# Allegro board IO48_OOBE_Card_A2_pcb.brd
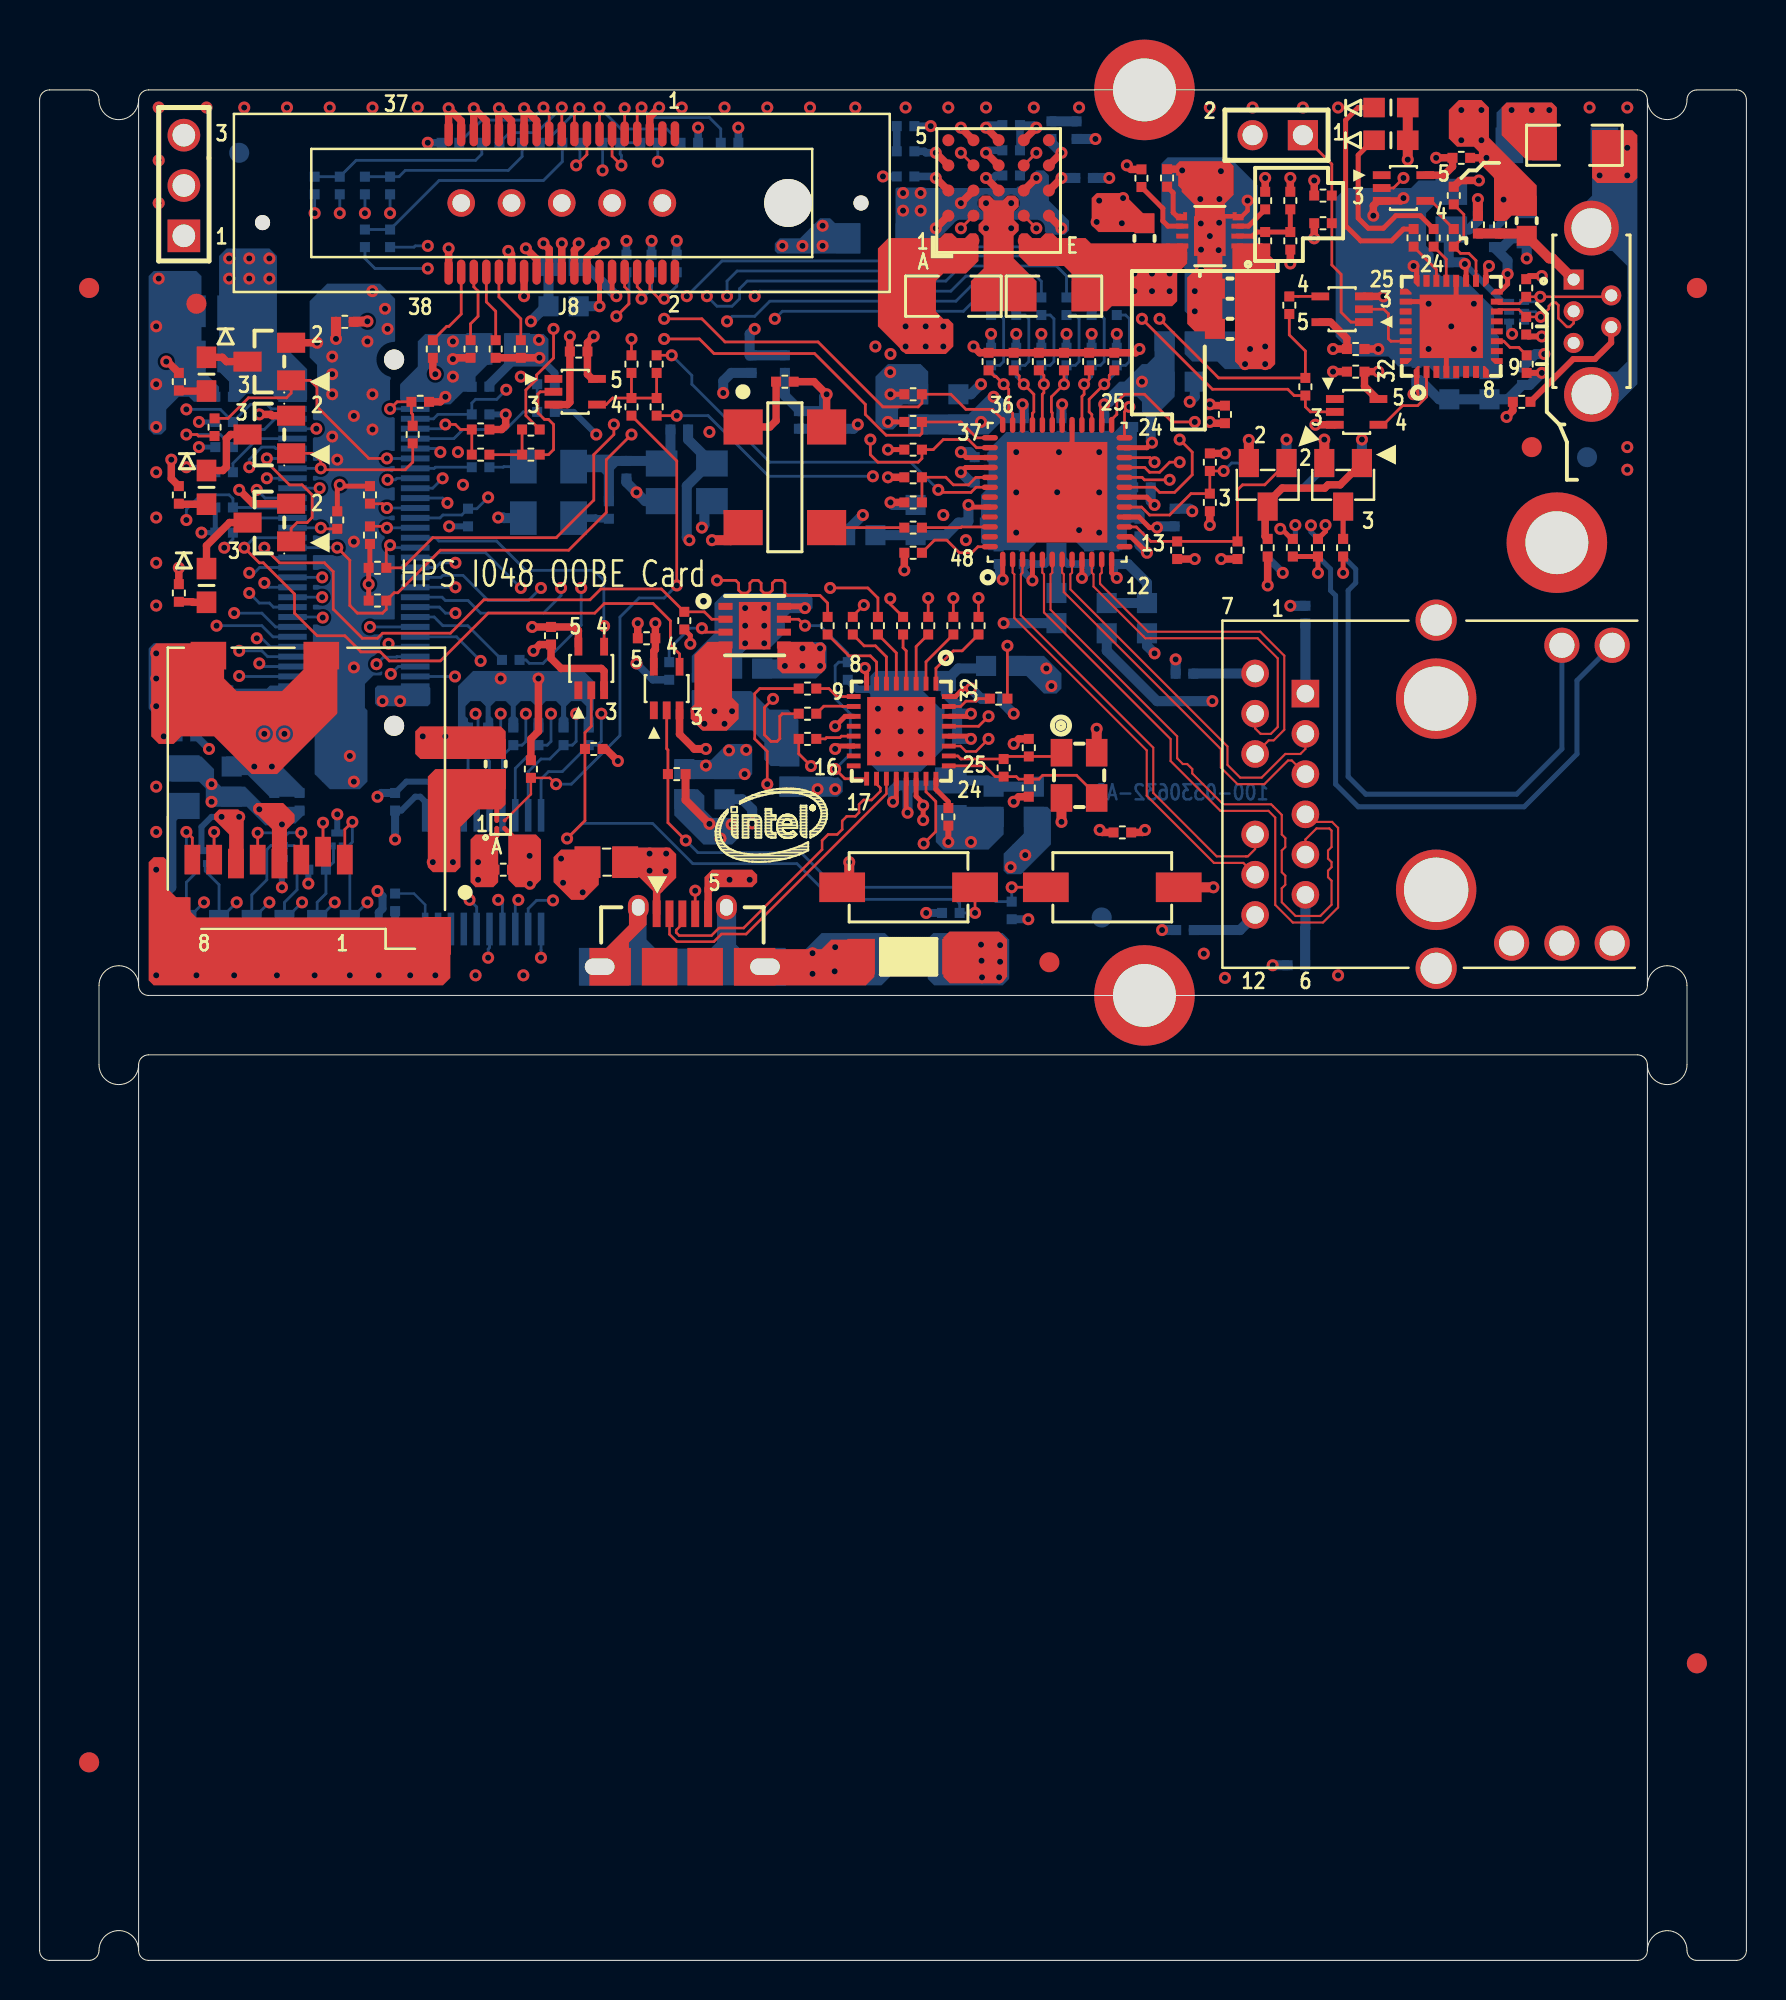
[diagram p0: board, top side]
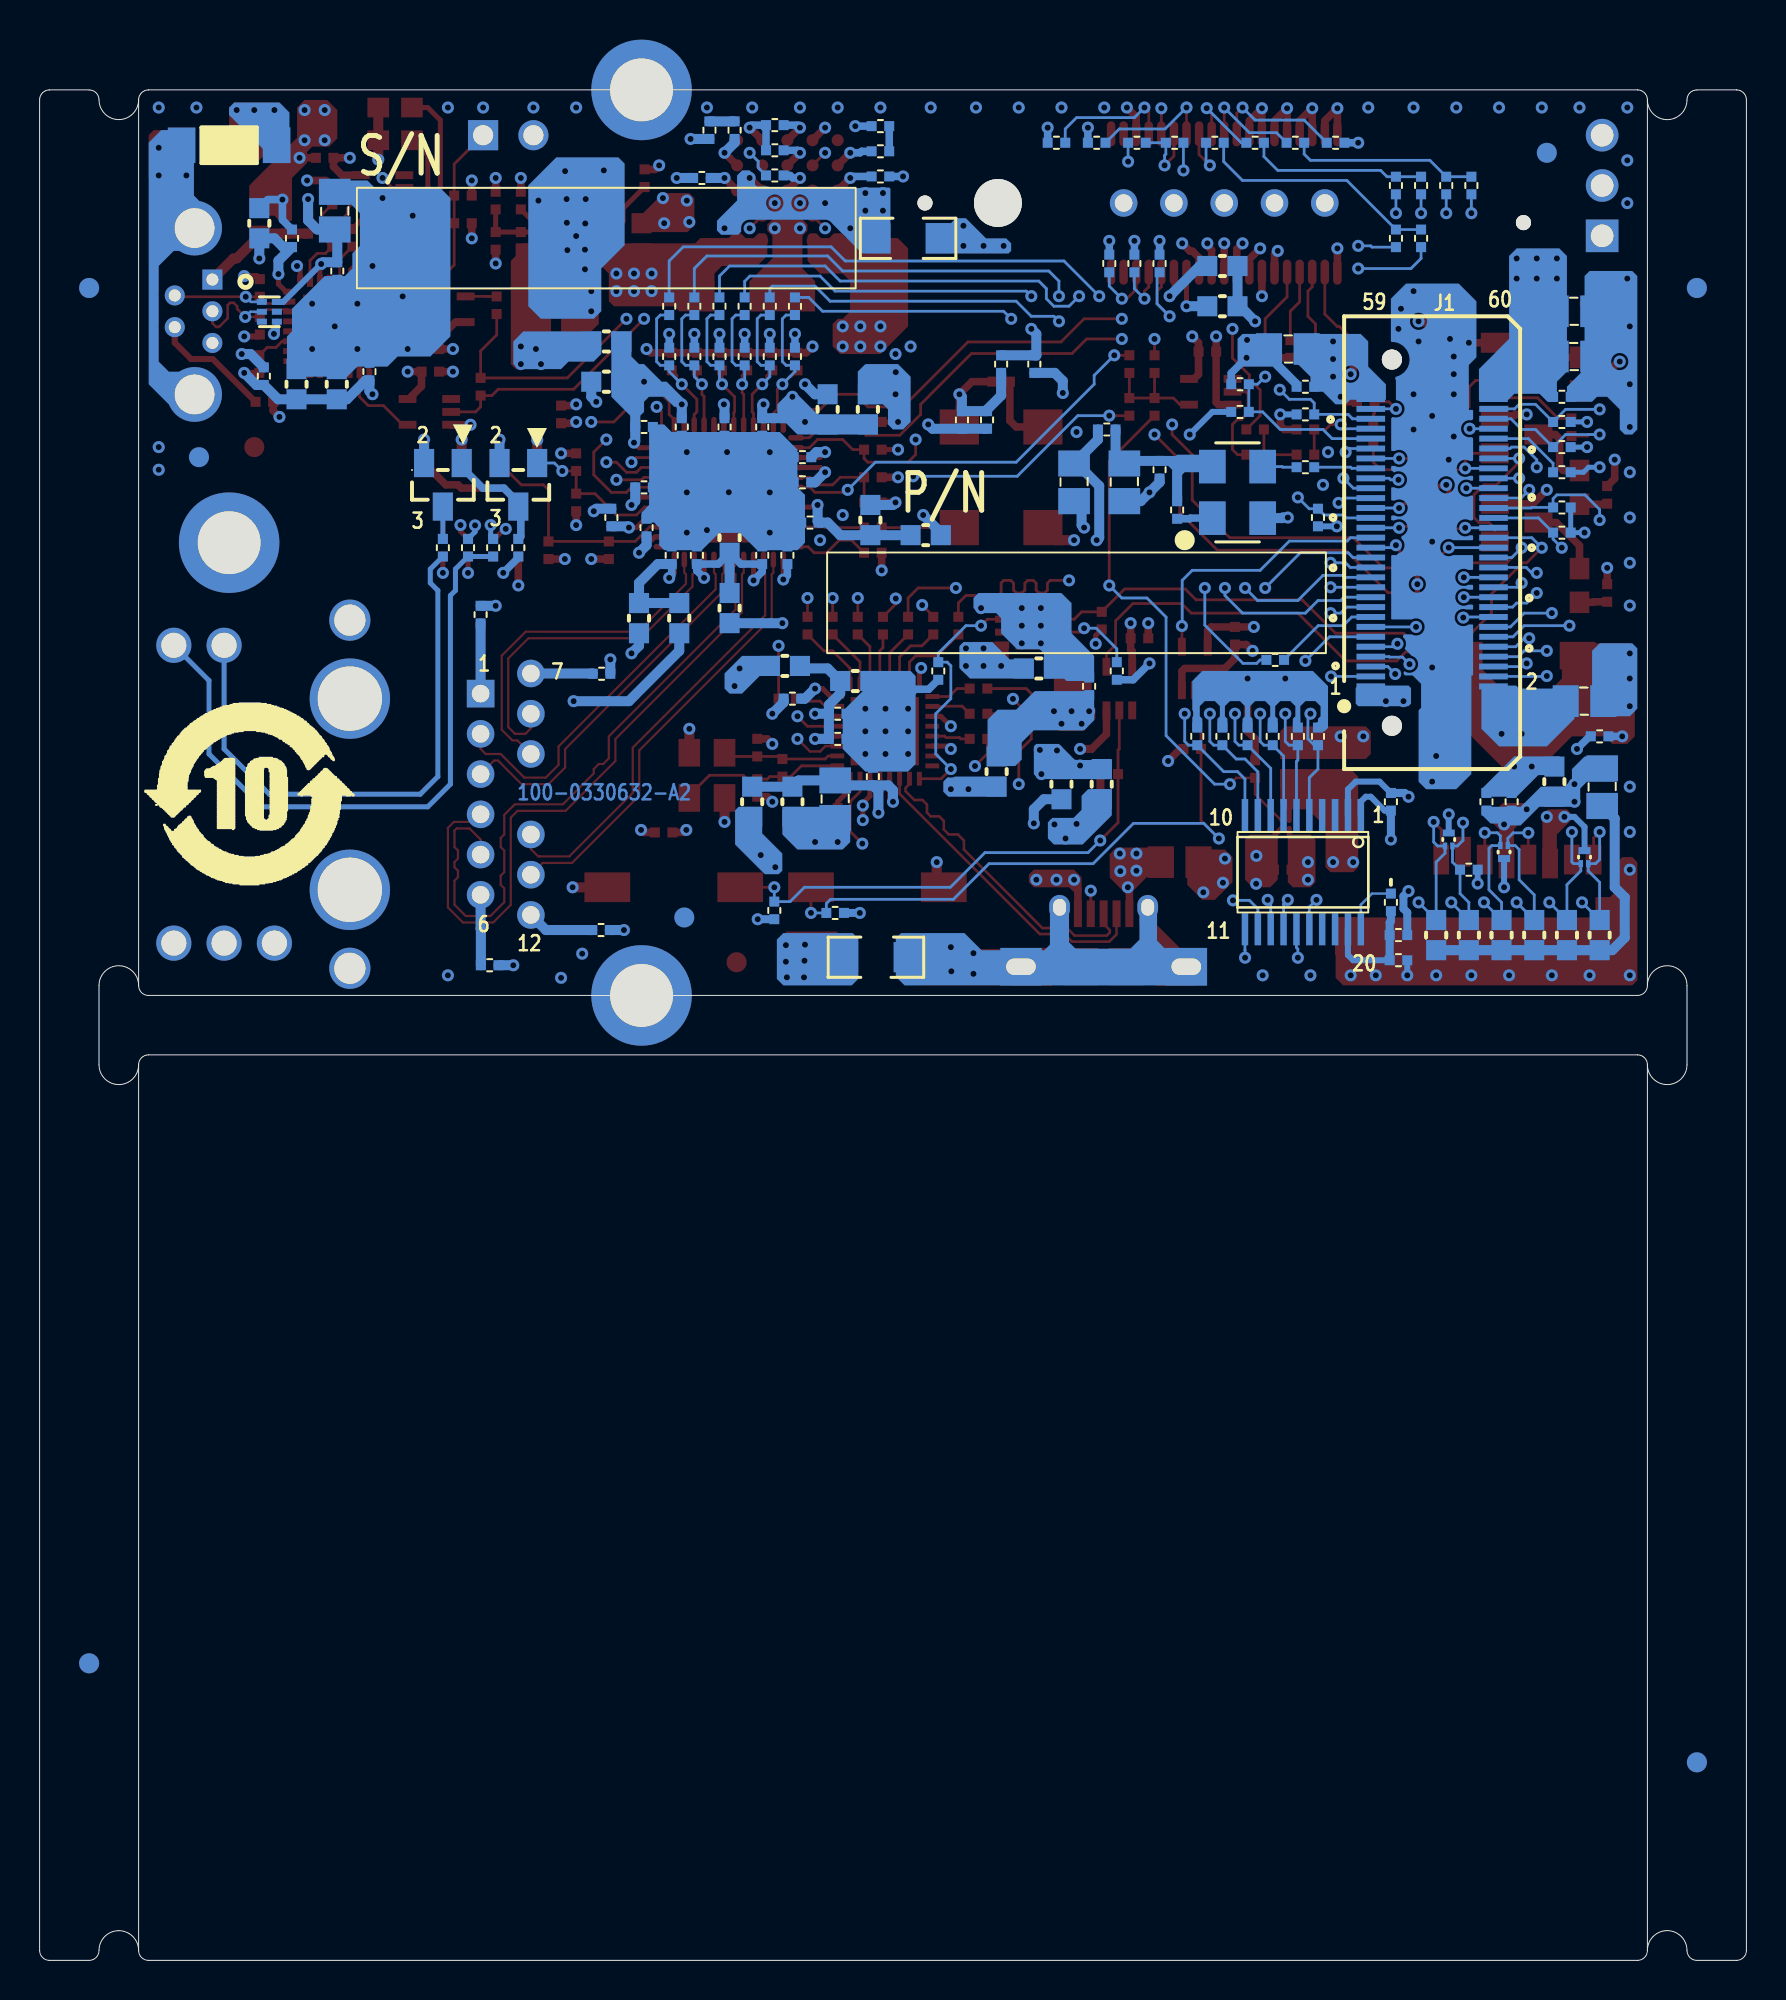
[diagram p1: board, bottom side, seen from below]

Outline 86.2 x 94.44 mm; copper layers: TOP, L2_GND, L3_SIG, L4_PWR, L5_GND, L6_SIG, L7_GND, BOTTOM. Coordinates in mm from the lower left corner of the outline.
Outline path: 5,49.22 arc(4,50.22) 3,49.22 3,45.22 arc(4,44.22) 5,45.22 ; 5,49.22 5,93.94 ; 5,49.22 arc(5.15,48.87) 5.5,48.72 80.7,48.72 arc(81.05,48.87) 81.2,49.22 ; 5,0.5 arc(3.99,1.5) 3,0.48 arc(2.85,0.14) 2.5,0 0.5,0 arc(0.15,0.15) 0,0.5 0,93.94 arc(0.15,94.29) 0.5,94.44 2.5,94.44 arc(2.85,94.29) 3,93.94 arc(4,92.94) 5,93.94 ; 5,0.5 5,45.22 ; 5,0.5 arc(5.15,0.15) 5.5,0 80.7,0 arc(81.05,0.15) 81.2,0.5 ; 5,93.94 arc(5.15,94.29) 5.5,94.44 80.7,94.44 arc(81.05,94.29) 81.2,93.94 ; 5,45.22 arc(5.15,45.57) 5.5,45.72 80.7,45.72 arc(81.05,45.57) 81.2,45.22 ; 81.2,93.94 81.2,49.22 ; 81.2,93.94 arc(82.21,92.94) 83.2,93.96 arc(83.35,94.3) 83.7,94.44 85.7,94.44 arc(86.05,94.29) 86.2,93.94 86.2,0.5 arc(86.05,0.15) 85.7,0 83.7,0 arc(83.35,0.15) 83.2,0.5 arc(82.2,1.5) 81.2,0.5 ; 81.2,45.22 81.2,0.5 ; 81.2,45.22 arc(82.2,44.22) 83.2,45.22 83.2,49.22 arc(82.2,50.22) 81.2,49.22

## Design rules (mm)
net group ENET_GTX_CLK: nets ENET_GTX_CLK N134431006
net group ENET_VDD1.2V: nets ENET_VDD1.2V N134306486
net group MDI_HPS_N0: nets MDI_HPS_N0 MDI_HPS_P0
net group MDI_HPS_N1: nets MDI_HPS_N1 MDI_HPS_P1
net group MDI_HPS_N2: nets MDI_HPS_N2 MDI_HPS_P2
net group MDI_HPS_N3: nets MDI_HPS_N3 MDI_HPS_P3
net group USB_D: nets USB_D_N USB_D_P
net group USB_UART_DM: nets USB_UART_DM USB_UART_DP
net group VCC_3.3V: nets N134303911 VCC_3.3V
net group CLK125_NDO_LED_MODE: nets CLK125_NDO_LED_MODE E_RX_CLK E_RXD0 E_RXD1 E_RXD2 E_RXD3 ENET_1.8V_DVDDH
net group CLS_JTAG_FPGA: nets FPGA_JTAG_TCK FPGA_JTAG_TDI FPGA_JTAG_TDO FPGA_JTAG_TMS
net group CLS_JTAG_HPS: nets HPS_JTAG_TCK HPS_JTAG_TDI HPS_JTAG_TDO HPS_JTAG_TMS
net group CLS_JTAG_MICTOR: nets MICTOR_JTAG_TCK MICTOR_JTAG_TDI MICTOR_JTAG_TDO MICTOR_JTAG_TMS
net group CLS_SD: nets SD_CLK_3.3V SD_CMD_3.3V SD_DATA0_3.3V SD_DATA1_3.3V SD_DATA2_3.3V SD_DATA3_3.3V
net group ENET: nets E_RX_DV ENET_INTN ENET_RX_CLK ENET_RX_DV ENET_RXD0 ENET_RXD1 ENET_RXD2 ENET_RXD3 ENET_TX_EN ENET_TXD0 ENET_TXD1 ENET_TXD2 ENET_TXD3
net group FT232R_VCCIO: nets UART_RESETN
net group POWER: nets CT0 CT1 CT2 CT3 ENET_1.2V_AVDDL ENET_1.2V_AVDLL_PLL ENET_1.2V_DVDDL ENET_3.3V_AVDDH FT232R_3V3OUT FT232R_VCCIO GND HPS_OSC_CLK_1.8V INTVCC MICTOR_PWR1 MINI_USB_PGND N134005839 N134057943 N134063078 N134121389 N134242750 N134242873 N134242878 N134242888 N134243679 N134244009 N134244011 N134244826 N134304469 N134306474 N134368065 PHY_25M_3.3V PWN_EN SD_3.3V USB_5V USB_RBIAS USB_UART_5V USB_UART_CON_5V USB_VBAT USB_VBUS USB_VDD18 USB_VDDIO VCC_5V VCC_12V VCCIO_HPS VREF_B
net group SD: nets SD_CLK SD_CMD SD_DATA0 SD_DATA1 SD_DATA2 SD_DATA3
net group USB: nets N134344647 N134344648 N134344649 N134344650 N134344651 N134344652 N134344653 N134344654 USB_CLK USB_CLKR USB_DATA0 USB_DATA1 USB_DATA2 USB_DATA3 USB_DATA4 USB_DATA5 USB_DATA6 USB_DATA7 USB_DIR USB_DIRR USB_NXT USB_NXTR USB_STP

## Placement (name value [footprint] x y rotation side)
C1  4.7uF  [0805]  23.16 81.36 270 bottom
C2  0.1uF  [0402]  22.27 79.45 90 bottom
C3  4.7uF  [0805]  8.68 80.98 90 bottom
C4  0.1uF  [0402]  9.32 78.95 270 bottom
C5  0.01uF  [0402]  57.84 52.02 90 bottom
C6  0.01uF  [0402]  63.47 50.24 90 bottom
C7  0.01uF  [0402]  63.93 67.95 0 bottom
C8  0.01uF  [0402]  57.82 64.96 90 bottom
C11  22uF  [0603]  55.93 67.77 270 bottom
C13  0.1uF  [0402]  48.43 70.94 180 bottom
C15  22uF  [0603]  46.4 78.31 90 bottom
C17  0.1uF  [0402]  49.7 77.42 0 bottom
C18  22uF  [0603]  44.24 72.72 90 bottom
C20  0.01uF  [0402]  47.29 72.6 90 bottom
C23  22uF  [0603]  51.35 71.83 90 bottom
C25  0.01uF  [0402]  49.7 70.94 180 bottom
C26  22uF  [0603]  60.12 84.41 180 top
C28  2.2uF  [0603]  60.12 82.37 180 top
C29  22uF  [0603]  57.58 79.71 0 bottom
C31  0.1uF  [0402]  47.67 75.9 90 bottom
C32  2.2uF  [0603]  35.73 65.23 180 bottom
C33  0.1uF  [0402]  33.19 64.33 180 bottom
C34  4.7uF  [0805]  46.02 58.63 180 bottom
C35  0.1uF  [0402]  44.12 59.77 180 bottom
C36  0.1uF  [0402]  45.89 62.94 270 bottom
C37  0.1uF  [0402]  48.18 63.71 90 bottom
C38  0.1uF  [0402]  45.89 61.67 270 bottom
C39  4.7uF  [0805]  28.62 55.45 270 top
C40  30pF  [0402]  49.96 59.2 0 top
C41  30pF  [0402]  49.96 61.23 180 top
C42  2.2uF  [0603]  9.7 59.51 90 bottom
C43  0.1uF  [0402]  11.86 58.5 180 bottom
C44  0.1uF  [0402]  13.13 58.5 180 bottom
C45  0.1uF  [0402]  17.95 58.5 0 bottom
C46  0.1uF  [0402]  17.57 50.5 270 bottom
C47  0.1uF  [0402]  23.41 55.07 270 top
C48  2.2uF  [0603]  23.03 60.4 90 top
C53  39pF  [0402]  75.08 84.44 180 top
C54  39pF  [0402]  75.08 82.54 0 top
C55  0.1uF  [0402]  73.45 86.95 180 bottom
C56  2.2uF  [0603]  75.1 87.71 90 bottom
C57  0.1uF  [0402]  69.54 80.22 180 bottom
C58  2.2uF  [0603]  71.19 79.58 90 bottom
C59  0.1uF  [0402]  71.17 85.3 0 bottom
C60  4.7uF  [0805]  71.29 88.34 0 bottom
C61  0.01uF  [0402]  73.76 87.63 0 top
C62  0.1uF  [0402]  46.02 52.89 270 bottom
C63  0.1uF  [0402]  49.09 53.01 0 bottom
C896  10uF  [1206]  42.34 86.95 180 bottom
C900  47uF  [1206]  51.23 84.03 0 top
C903  47uF  [1206]  46.15 84.03 180 top
C909  0.1uF  [0402]  27.23 81.23 270 top
C914  22uF  [0603]  48.18 58.5 270 bottom
C915  22uF  [0603]  34.59 59.39 270 bottom
C916  22uF  [0603]  45.01 64.59 180 bottom
C919  22uF  [0603]  73.22 79.58 90 bottom
C920  22uF  [0603]  75.1 87.84 90 top
C921  0.01uF  [0402]  52.75 89.99 270 bottom
C922  0.01uF  [0402]  43.73 90.07 90 bottom
C924  0.01uF  [0402]  35.96 80.6 0 bottom
C925  0.01uF  [0402]  39.62 77.78 0 bottom
C927  0.01uF  [0402]  38.35 77.78 0 bottom
C928  22uF  [0603]  55.8 86.95 90 top
C929  1nF  [0402]  56.94 89.99 0 top
C930  120pF  [0402]  61.9 86.82 0 top
C931  0.01uF  [0402]  53.01 70.94 180 bottom
C932  0.1uF  [0402]  51.61 77.42 0 bottom
C933  0.1uF  [0402]  53.77 77.42 0 bottom
C934  0.1uF  [0402]  55.67 77.42 270 bottom
C935  0.1uF  [0402]  55.67 74.37 270 bottom
C936  0.1uF  [0402]  55.55 72.34 180 bottom
C937  0.1uF  [0402]  54.28 70.94 180 bottom
C938  0.1uF  [0402]  47.67 74.63 90 bottom
C939  0.1uF  [0402]  57.32 72.85 180 bottom
C940  DNI  [1808]  43.89 50.68 180 top
C943  DNI  [1808]  76.63 91.65 0 bottom
C944  0.1uF  [0402]  71.8 91.01 90 top
C945  0.1uF  [0402]  66.47 80.22 270 top
C946  0.1uF  [0402]  66.47 81.36 90 top
C953  0.1uF  [0402]  29.64 75.26 0 bottom
C954  10uF  [C0805]  33.96 74.63 180 bottom
C955  10uF  [C0805]  31.42 74.63 180 bottom
C956  0.1uF  [0402]  30.65 66.75 270 top
C957  0.1uF  [0402]  25.83 66.88 0 top
C958  4.7uF  [0805]  8.18 63.58 90 bottom
C959  4.7uF  [0805]  8.68 83.26 90 bottom
C960  0.1uF  [0402]  59.86 78.06 0 top
C961  0.1uF  [0402]  7.41 61.8 270 bottom
C962  0.1uF  [0402]  54.68 56.95 90 top
C963  0.1uF  [0402]  15.41 82.73 90 top
C964  0.1uF  [0402]  64.56 71.33 0 top
C965  0.1uF  [0402]  64.56 71.33 0 bottom
D1  ESD5V3U2U  [TSLP-3-7]  15.03 56.59 180 bottom
D2  ESD5V3U2U  [TSLP-3-7]  8.18 55.7 180 bottom
D3  ESD5V3U2U  [TSLP-3-7]  12.24 55.96 0 bottom
D4  GREEN_LED  [LED_0603]  68.25 93.55 180 top
D5  GREEN_LED  [LED_0603]  68.25 91.9 180 top
D6  GREEN_LED  [LED_0603]  8.43 80.09 90 top
D7  GREEN_LED  [LED_0603]  8.43 69.42 90 top
D8  GREEN_LED  [LED_0603]  8.43 74.37 90 top
J1  QTH-030-02-L-D-A  [QTH-030]  15.87 71.58 90 bottom
J2  HEADER, 1x3-PIN  [CONN_TSW_103_07_L_S]  7.29 87.07 90 top
J3  ENET_L829-1J1T-43  [BEL_L829-1J1T-43]  63.93 63.96 270 top
J4  MICRO_USB_CONN  [MOLEX-MICRO-USB-47589-001]  31.16 52.86 180 top
J5  MicroSD_skt  [WURTH_MICRO-SD_CARD]  15.41 55.58 180 top
J7  USB MINI-B-SMT Vertical  [MINI_USB_SMTB]  78.37 83.26 90 top
J8  Mictor38P  [SMT38]  26.37 88.73 0 top
J10  CON2  [HDR2X1_100MIL]  63.8 92.15 180 top
J11  mounting hole  [C635TC317-01]  55.8 48.72 0 top
J12  mounting hole  [C635TC317-01]  55.8 94.44 0 top
J13  mounting hole  [C635TC317-01]  76.63 71.58 0 top
L1  3A, 30 Ohm FB  [IND_0603]  53.9 67.77 90 bottom
L2  3A, 30 Ohm FB  [IND_0603]  44.37 78.31 270 bottom
L3  3A, 30 Ohm FB  [IND_0603]  41.45 71.96 0 bottom
L4  3A, 30 Ohm FB  [IND_0603]  51.35 68.28 90 bottom
L5  3A, 30 Ohm FB  [IND_0603]  57.58 81.74 180 bottom
L6  742792780  [0402]  72.64 87.63 0 top
L9  742792780  [0402]  65.83 71.33 180 bottom
L10  742792780  [0402]  65.83 71.33 0 top
NOREF  -  [unnamed]  7.92 83.64 0 top
NOREF#2  -  [unnamed]  83.7 84.44 0 top
NOREF#3  -  [unnamed]  2.5 10 0 top
NOREF#4  -  [unnamed]  51 50.4 0 top
NOREF#5  -  [unnamed]  83.7 15 0 top
NOREF#6  -  [unnamed]  2.5 84.44 0 top
NOREF#7  -  [unnamed]  75.36 76.41 0 top
NOREF#8  -  [unnamed]  83.7 84.44 180 bottom
NOREF#9  -  [unnamed]  2.5 10 180 bottom
NOREF#10  -  [unnamed]  2.5 84.44 180 bottom
NOREF#11  -  [unnamed]  53.64 52.66 180 bottom
NOREF#12  -  [unnamed]  10.08 91.26 180 bottom
NOREF#13  -  [unnamed]  78.15 75.9 180 bottom
NOREF#14  -  [unnamed]  83.7 15 180 bottom
Q1  FDV305N  [SOT23]  11.6 80.72 90 top
Q2  FDV305N  [SOT23]  11.6 72.6 90 top
Q3  FDV305N  [SOT23]  11.6 77.04 90 top
Q4  FDV305N  [SOT23]  62.02 74.5 180 top
Q5  FDV305N  [SOT23]  65.83 74.5 180 top
Q6  FDV305N  [SOT23]  62.02 74.5 0 bottom
Q7  FDV305N  [SOT23]  65.83 74.5 0 bottom
R1  0  [0402]  9.32 75.14 90 bottom
R4  4.7K  [0402]  44.12 79.07 90 top
R6  4.7K  [0402]  44.12 77.68 90 top
R7  4.7K  [0402]  22.27 77.29 270 top
R8  33  [0402]  48.05 83.52 0 bottom
R9  220  [0402]  63.29 71.33 180 bottom
R10  4.7K  [0402]  44.12 76.28 90 top
R11  33  [0402]  49.32 83.52 0 bottom
R12  33  [0402]  50.59 83.52 0 bottom
R13  33  [0402]  51.86 83.52 0 bottom
R14  33  [0402]  53.13 83.52 0 bottom
R15  33  [0402]  54.4 83.52 0 bottom
R16  220  [0402]  63.29 71.33 0 top
R17  12.1K  [0402]  44.12 71.07 270 top
R18  DNI  [0402]  57.45 71.2 180 top
R19  4.7K  [0402]  60.5 71.2 0 top
R20  10K  [0402]  37.64 79.71 270 top
R21  75  [0402]  44.12 72.34 90 top
R22  DNI  [0402]  59.1 75.64 0 top
R23  4.7K  [0402]  59.1 73.61 0 top
R25  4.7K  [0402]  54.28 80.72 0 top
R26  DNI  [0402]  54.4 80.98 0 bottom
R27  4.7K  [0402]  53.01 80.72 0 top
R28  DNI  [0402]  53.13 80.98 0 bottom
R29  4.7K  [0402]  51.74 80.72 0 top
R30  DNI  [0402]  51.86 80.98 0 bottom
R31  4.7K  [0402]  50.47 80.72 0 top
R32  DNI  [0402]  50.59 80.98 0 bottom
R33  DNI  [0402]  49.2 80.72 0 top
R34  4.7K  [0402]  49.32 80.98 0 bottom
R35  4.7K  [0402]  47.93 80.72 0 top
R36  DNI  [0402]  48.05 80.98 0 bottom
R37  4.7K  [0402]  44.12 74.88 90 top
R38  DNI  [0402]  44.12 73.61 270 top
R39  1.87K  [0402]  63.17 86.82 180 top
R42  137K  [0402]  31.8 65.1 180 bottom
R44  0  [0603]  48.56 65.36 180 bottom
R45  10K  [0402]  40.81 65.1 180 bottom
R46  0  [0603]  32.56 59.39 90 bottom
R47  0  [0603]  50.21 58.5 90 bottom
R54  1.00K  [0603]  37.87 60.02 270 bottom
R59  33  [0402]  47.42 67.39 0 top
R60  33  [0402]  46.15 67.39 0 top
R61  33  [0402]  48.43 63.71 270 top
R62  1M  [0402]  48.69 60.21 0 top
R63  8.06K  [0402]  45.89 57.74 180 top
R66  200K  [0402]  17.57 51.77 90 bottom
R67  0.1  [0805]  7.29 59.24 180 bottom
R70  499  [0603]  9.06 51.77 270 bottom
R72  499  [0603]  7.41 51.77 270 bottom
R73  499  [0603]  15.67 51.77 270 bottom
R74  499  [0603]  14.02 51.77 270 bottom
R75  330  [0603]  12.37 51.77 270 bottom
R76  330  [0603]  10.71 51.77 270 bottom
R78  DNI  [0402]  14.02 55.07 270 bottom
R79  DNI  [0402]  27.73 61.8 180 bottom
R80  1.00K  [0402]  26.46 61.8 180 bottom
R81  1.00K  [0402]  21.64 61.8 180 bottom
R82  1.00K  [0402]  22.65 61.8 180 bottom
R83  1.00K  [0402]  23.92 61.8 180 bottom
R84  1.00K  [0402]  25.19 61.8 180 bottom
R97  0  [0402]  74.88 79.99 180 bottom
R101  0  [0402]  74.85 78.69 270 top
R103  220  [0402]  69.39 86.97 180 top
R104  220  [0402]  70.41 86.97 180 top
R105  10K  [0402]  75.1 80.6 0 top
R106  10K  [0402]  34.84 91.77 270 bottom
R107  10K  [0402]  30.91 85.68 180 bottom
R109  DNI  [0402]  29.64 85.68 180 bottom
R110  0  [0603]  26.46 85.55 180 bottom
R111  DNI  [0603]  26.46 83.52 180 bottom
R112  10K  [0402]  20.75 91.77 90 bottom
R113  10K  [0402]  24.3 81.36 180 top
R114  10K  [0402]  23.03 81.36 180 top
R115  10K  [0402]  21.76 81.36 180 top
R116  10K  [0402]  19.86 81.36 180 top
R117  0  [0402]  17.7 86.95 0 bottom
R118  0  [0402]  16.43 86.95 0 bottom
R119  0  [0402]  17.7 89.61 0 bottom
R120  0  [0402]  16.43 89.61 0 bottom
R121  0  [0402]  13.89 89.61 0 bottom
R122  0  [0402]  15.16 89.61 0 bottom
R123  0  [0402]  30.78 91.77 90 bottom
R124  0  [0402]  28.88 91.77 270 bottom
R125  10K  [0402]  27.99 61.17 90 top
R126  220  [0402]  7.03 79.71 0 top
R127  220  [0402]  7.03 69.04 0 top
R128  10K  [0402]  32.18 59.9 90 top
R129  220  [0402]  7.03 73.99 0 top
R131  10K  [0402]  28.75 73.23 180 bottom
R456  13.3K  [0402]  51.1 92.41 180 bottom
R612  1.00K  [0402]  49.07 92.66 270 bottom
R667  324K  [R0402]  49.07 91.39 90 bottom
R668  0  [0402]  52.37 92.41 0 bottom
R669  8.25K  [0402]  43.73 91.34 270 bottom
R670  0  [0402]  43.73 92.61 90 bottom
R671  DNI  [0402]  49.07 90.12 90 bottom
R675  4.7K  [0402]  32.56 67.64 180 top
R681  DNI  [0402]  8.84 77.41 180 top
R682  DNI  [0402]  18.84 77.04 0 top
R683  22  [0402]  22.27 76.02 90 top
R684  22  [0402]  24.81 77.29 90 top
R685  330  [0402]  24.81 76.02 270 top
R686  4.7K  [0402]  9.32 76.41 270 bottom
R687  4.7K  [0402]  19.22 78.69 270 top
R688  4.7K  [0402]  9.32 77.68 270 bottom
R689  4.7K  [0402]  9.32 73.36 270 bottom
R690  4.7K  [0402]  9.32 72.09 270 bottom
R691  4.7K  [0402]  16.68 73.99 0 top
R692  1.00K  [0402]  21.64 72.85 180 bottom
R693  1.00K  [0402]  22.27 78.06 270 bottom
R694  4.7K  [0402]  16.68 71.96 180 top
R695  4.7K  [0402]  15.03 72.72 0 top
R696  4.7K  [0402]  17.06 68.66 90 top
R697  4.7K  [0402]  17.06 70.31 90 top
R698  1.00K  [0402]  25.57 79.58 90 bottom
R699  2.61K  [0402]  63.17 88.85 0 top
R5262  4.7K  [0402]  55.65 89.98 180 top
R5265  4.7K  [0402]  61.9 88.85 180 top
R5266  0  [1206]  43.96 50.65 0 bottom
R5269  0  [1206]  77.52 91.65 180 top
R5270  DNI  [0402]  71.42 86.97 0 top
R5271  4.7K  [0402]  71.42 89.11 0 top
R5275  10K  [0402]  32.81 91.77 270 bottom
R5276  10K  [0402]  32.18 85.68 180 bottom
R5283  DNI  [0402]  63.93 79.45 180 top
R5284  1.00K  [0402]  64.82 87.71 90 top
R5285  DNI  [0402]  64.82 89.11 270 top
R5286  0  [0402]  17.95 53.42 180 bottom
R5287  33  [0402]  31.16 80.6 180 top
R5288  33  [0402]  31.16 78.44 0 top
R5289  33  [0402]  29.89 78.44 0 top
R5290  33  [0402]  29.89 80.6 180 top
R5291  33  [0402]  22.27 75.39 90 bottom
R5292  33  [0402]  44.88 67.39 0 top
R5293  33  [0402]  43.61 67.39 0 top
R5294  33  [0402]  42.34 67.39 0 top
R5295  33  [0402]  41.07 67.39 0 top
R5296  33  [0402]  39.8 67.39 0 top
R5297  33  [0402]  38.78 64.21 90 top
R5298  33  [0402]  38.78 62.94 90 top
R5299  33  [0402]  38.78 61.67 90 top
R5300  33  [0402]  63.12 83.57 180 top
R5301  33  [0402]  26.84 91.77 270 bottom
R5302  33  [0402]  24.81 91.77 270 bottom
R5303  33  [0402]  22.78 91.77 270 bottom
R5304  1.00K  [0402]  62.02 71.33 180 top
R5305  1.00K  [0402]  62.02 71.33 0 bottom
R5306  4.7K  [0402]  24.81 60.15 180 top
R5307  DNI  [0402]  25.57 78.18 270 bottom
R5308  0  [0402]  37.64 80.6 180 bottom
R5309  0  [0402]  32.3 77.29 90 bottom
R5311  0  [0402]  23.8 65.66 90 bottom
S1  PB Switch  [WURTH_6X3P5_TACT_SWITCH]  43.89 54.18 0 top
S2  PB Switch  [WURTH_6X3P5_TACT_SWITCH]  54.17 54.18 180 top
U1  KSZ9031RN  [QFN48]  51.39 74.13 90 top
U3  MAX14523B  [TDFN-8]  36.11 67.39 270 top
U4  USB3320  [QFN32]  43.52 62.06 270 top
U5  LSF0108PWR  [TSSOP20]  22.4 54.94 270 bottom
U6  -  [TPS22902BYFPR]  23.29 57.36 90 top
U9  FT232R  [QFN32-FTDI]  71.29 82.5 90 top
U10  TPD4S012DRYR  [SON6]  74.6 83.24 270 bottom
U15  LTM4622EY  [BGA25]  48.43 89.36 90 top
U62  EY1501DI-ADJ  [DFN-10]  59.1 87.06 180 top
U63  SN74AUP1G126DCK  [SC70_TI]  65.78 83.37 90 top
U64  SN74AUP1T17DCKR  [SC70_TI]  68.88 89.49 270 top
U65  SN74AUP1T17DCKR  [SC70_TI]  66.52 78.18 270 top
U68  SN74AUP1G17DCK  [SC70_TI]  27.05 79.2 270 top
U69  SN74AUP1G17DCK  [SC70_TI]  27.86 65.23 0 top
U70  SN74AUP1G17DCK  [SC70_TI]  31.67 64.21 0 top
Y1  24MHz  [XTAL_ECX-32]  52.5 59.83 270 top
Y2  25MHz  [OSC3250]  25.7 74.12 90 bottom
Y3  25MHz  [OSC7050]  37.64 74.88 270 top

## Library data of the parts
C1-C8 C13 C17 C20 C25 C31 C33-C41 C43-C47 C55 C57 C59-C63 C909 C921 C922 C924 C925 C927 C929-C939 C944-C946 C953-C965 = CAP: Tolerance: TOL; User Part Number: PART#
C11 C15 C18 C23 C26 C28 C29 C32 C42 C48 C56 C58 C914-C916 C919 C920 C928 = CAP: User Part Number: *; Tolerance: *
C53 C54 = Cap 39PF 5% 50V 0402: Tolerance: TOL; User Part Number: PART#
C896 C900 C903 = CAP
C940 C943 = CAP: User Part Number: CC4520R01A; Tolerance: ?
D1-D3 = ESD_DIODE_DUAL: User Part Number: *
D4-D8 = LED_WURTH: Tolerance: *; User Part Number: *
J1 = HEADER 30X2_0
J2 = HEADER, 1x3-PIN: User Part Number: *
J3 = ENET_L829-1J1T-43_2: Tolerance: *; User Part Number: *
J4 = MICRO_USB_CONN
J5 = SD_SKT_1: User Part Number: *
J7 = USB_MINI_B_SMT
J8 = 2-767004-2
J10 = CON2: User Part Number: *
J11-J13 = mounting hole: Tolerance: ?; User Part Number: ***********
L1-L5 = IND Ferrite 0603 3A/30 Ohms: Tolerance: *; User Part Number: *
L6 L9 L10 = BEAD_FERRITE_SM: Tolerance: TOL; User Part Number: PART#
Q1-Q7 = NMOS_3Pin: User Part Number: *; Tolerance: *
R1 R8 R9 R11-R18 R20-R22 R26 R28 R30 R32 R33 R36 R38 R39 R45 R59-R63 R66 R67 R78-R84 R97 R101 R103-R107 R109 R112-R129 R131 R612 R668 R670 R671 R681-R685 R692 R693 R698 R5270 R5275 R5276 R5283-R5305 R5307-R5309 = RESISTOR: Tolerance: TOL; User Part Number: PART#
R4 R6 R7 R10 R19 R23 R25 R27 R29 R31 R34 R35 R37 R675 R686-R691 R694-R697 R5262 R5265 R5271 R5306 = RESISTOR: Tolerance: TOL; User Part Number: PART#; signal model: RESISTOR_0402_4.7K_4.7K
R42 = RES 178K Ohm 1% 1/10W 0402: Tolerance: TOL; User Part Number: PART#
R44 R46 R47 R54 R70 R72-R76 R110 R111 = RESISTOR: User Part Number: *; Tolerance: *
R456 R669 = RESISTOR_0402: Tolerance: TOL; User Part Number: PART#
R667 = Resistor, 0402: Tolerance: TOL; User Part Number: PART#
R699 = R: Tolerance: TOL; User Part Number: PART#
R5266 R5269 = RESISTOR
R5311 = RESISTOR: Tolerance: TOL; User Part Number: PART#; signal model: RESISTOR_0402_0_0
S1 S2 = TS-A02SA-2-S100_0: User Part Number: *
U1 = KSZ9031RN_4: User Part Number: *
U3 = MAX14523B: User Part Number: *
U4 = USB3320: User Part Number: *
U5 = LSF0108PWR: Tolerance: ***; User Part Number: ***
U6 = TPS22902BYFPR
U9 = FT232R_2: User Part Number: *
U10 = TPD4S012DRYR: User Part Number: *
U15 = LTM4622EV
U62 = EY1501DI-ADJ
U63 = SN74AUP1G126DCK
U64 U65 U68-U70 = SN74AUP1G17DCK
Y1 = CRYSTALSM_ECS: User Part Number: *
Y2 = OSC_ALT
Y3 = OSC_ALT: User Part Number: *; Tolerance: *

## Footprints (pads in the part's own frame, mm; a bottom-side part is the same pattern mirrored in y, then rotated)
0402
  rect 0.508x0.508 smd: 1(0,0.445) 2(0,-0.445)
0603
  rect 1.016x1.016 smd: 1(-0.762,0) 2(0.762,0)
0805
  rect 1.6x1.321 smd: 1(0,0.95) 2(0,-0.95)
1206
  rect 1.27x1.524 smd: 1(-1.524,0) 2(1.524,0)
1808
  rect 1.4x1.8 smd: 1(-2.4,0) 2(2.4,0)
BEL_L829-1J1T-43
  round 4.064 hole 3.251: (0.254,6.604) (9.906,6.604)
  rect 1.397x1.397 hole 0.889: 1(0,0)
  round 1.397 hole 0.889: 2(2.032,0) 3(4.064,0) 4(6.096,0) 5(8.128,0) 6(10.16,0) 7(-1.016,-2.54) 8(1.016,-2.54) 9(3.048,-2.54) 10(7.112,-2.54) 11(9.144,-2.54) 12(11.176,-2.54)
  round 1.778 hole 1.27: 13(-2.438,12.954) 14(-2.438,15.494) 15(12.598,10.414) 16(12.598,12.954) 17(12.598,15.494)
  round 2.083 hole 1.575: 18(-3.708,6.604) 19(13.868,6.604)
BGA25
  round 0.61 smd: A1(-2.54,2.54) A2(-1.27,2.54) A3(0,2.54) A4(1.27,2.54) A5(2.54,2.54) B1(-2.54,1.27) B2(-1.27,1.27) B3(0,1.27) B4(1.27,1.27) B5(2.54,1.27) C1(-2.54,0) C2(-1.27,0) C3(0,0) C4(1.27,0) C5(2.54,0) D1(-2.54,-1.27) D2(-1.27,-1.27) D3(0,-1.27) D4(1.27,-1.27) D5(2.54,-1.27) E1(-2.54,-2.54) E2(-1.27,-2.54) E3(0,-2.54) E4(1.27,-2.54) E5(2.54,-2.54)
C635TC317-01
  round 5.08 hole 3.175: 1(0,0)
C0805
  rect 1.6x1.321 smd: 1(0,0.95) 2(0,-0.95)
CONN_TSW_103_07_L_S
  rect 1.651x1.651 hole 1.143: 1(0,0)
  round 1.651 hole 1.143: 2(2.54,0) 3(5.08,0)
DFN-10
  custom 0.104x0.104 smd: 1(-1.425,1) 5(-1.425,-1) 6(1.425,-1) 10(1.425,1)
  rect 0.61x0.254 smd: 2(-1.395,0.5) 3(-1.395,0) 4(-1.395,-0.5) 7(1.395,-0.5) 8(1.395,0) 9(1.395,0.5)
  rect 1.6x2.007 smd: 11(0,0)
HDR2X1_100MIL
  rect 1.524x1.524 hole 1.016: 1(0,0)
  round 1.524 hole 1.016: 2(2.54,0)
IND_0603
  rect 1.016x1.016 smd: 1(-0.762,0) 2(0.762,0)
LED_0603
  rect 1.092x0.991 smd: A(-0.851,0) C(0.851,0)
MINI_USB_SMTB
  rect 1.016x1.016 hole 0.61: 1(1.6,0.9)
  round 1.016 hole 0.61: 2(0.8,-1) 3(0,0.9) 4(-0.8,-1) 5(-1.6,0.9)
  round 2.769 hole 2.007: 6(-4.2,0) 7(4.2,0)
MOLEX-MICRO-USB-47589-001
  rect 1.8x1.9 smd: (-2.45,2.686) (-0.15,2.686)
  rect 0.406x1.346 smd: 1(0,0.013) 2(-0.65,0.013) 3(-1.3,0.013) 4(-1.95,0.013) 5(-2.6,0.013)
  oval 1.05x1.25 hole 0.65x0.85: 6(-3.525,-0.314) 7(0.925,-0.314)
  rect 2.1x1.9 hole 1.5x0.83: 8(-5.475,2.686) 9(2.875,2.686)
OSC3250
  rect 1.7x1.35 smd: 1(-1.3,1.27) 2(-1.3,-1.27) 3(1.3,-1.27) 4(1.3,1.27)
OSC7050
  rect 1.778x1.981 smd: 1(-2.54,-2.109) 2(2.54,-2.109) 3(2.54,2.109) 4(-2.54,2.109)
QFN32
  rect 0.7x0.25 smd: 1(-2.4,1.75) 2(-2.4,1.25) 3(-2.4,0.75) 4(-2.4,0.25) 5(-2.4,-0.25) 6(-2.4,-0.75) 7(-2.4,-1.25) 8(-2.4,-1.75) 17(2.4,-1.75) 18(2.4,-1.25) 19(2.4,-0.75) 20(2.4,-0.25) 21(2.4,0.25) 22(2.4,0.75) 23(2.4,1.25) 24(2.4,1.75)
  rect 0.25x0.7 smd: 9(-1.75,-2.4) 10(-1.25,-2.4) 11(-0.75,-2.4) 12(-0.25,-2.4) 13(0.25,-2.4) 14(0.75,-2.4) 15(1.25,-2.4) 16(1.75,-2.4) 25(1.75,2.4) 26(1.25,2.4) 27(0.75,2.4) 28(0.25,2.4) 29(-0.25,2.4) 30(-0.75,2.4) 31(-1.25,2.4) 32(-1.75,2.4)
  rect 3.45x3.45 smd: 33(0,0)
QFN32-FTDI
  custom 0.075x0.075 smd: 1(-2.3,1.75) 8(-2.3,-1.75) 9(-1.75,-2.3) 16(1.75,-2.3) 17(2.3,-1.75) 24(2.3,1.75) 25(1.75,2.3) 32(-1.75,2.3)
  rect 0.61x0.305 smd: 2(-2.3,1.25) 3(-2.3,0.75) 4(-2.3,0.25) 5(-2.3,-0.25) 6(-2.3,-0.75) 7(-2.3,-1.25) 18(2.3,-1.25) 19(2.3,-0.75) 20(2.3,-0.25) 21(2.3,0.25) 22(2.3,0.75) 23(2.3,1.25)
  rect 0.305x0.61 smd: 10(-1.25,-2.3) 11(-0.75,-2.3) 12(-0.25,-2.3) 13(0.25,-2.3) 14(0.75,-2.3) 15(1.25,-2.3) 26(1.25,2.3) 27(0.75,2.3) 28(0.25,2.3) 29(-0.25,2.3) 30(-0.75,2.3) 31(-1.25,2.3)
  rect 3.2x3.2 smd: 33(0,0)
QFN48
  oval 0.813x0.279 smd: 1(-3.4,2.75) 2(-3.4,2.25) 3(-3.4,1.75) 4(-3.4,1.25) 5(-3.4,0.75) 6(-3.4,0.25) 7(-3.4,-0.25) 8(-3.4,-0.75) 9(-3.4,-1.25) 10(-3.4,-1.75) 11(-3.4,-2.25) 12(-3.4,-2.75) 25(3.4,-2.75) 26(3.4,-2.25) 27(3.4,-1.75) 28(3.4,-1.25) 29(3.4,-0.75) 30(3.4,-0.25) 31(3.4,0.25) 32(3.4,0.75) 33(3.4,1.25) 34(3.4,1.75) 35(3.4,2.25) 36(3.4,2.75)
  oval 0.279x0.813 smd: 13(-2.75,-3.4) 14(-2.25,-3.4) 15(-1.75,-3.4) 16(-1.25,-3.4) 17(-0.75,-3.4) 18(-0.25,-3.4) 19(0.25,-3.4) 20(0.75,-3.4) 21(1.25,-3.4) 22(1.75,-3.4) 23(2.25,-3.4) 24(2.75,-3.4) 37(2.75,3.4) 38(2.25,3.4) 39(1.75,3.4) 40(1.25,3.4) 41(0.75,3.4) 42(0.25,3.4) 43(-0.25,3.4) 44(-0.75,3.4) 45(-1.25,3.4) 46(-1.75,3.4) 47(-2.25,3.4) 48(-2.75,3.4)
  rect 5.08x5.08 smd: 49(0,0)
QTH-030
  round 1.016 hole 1.016 unplated: (-9.246,2.032) (9.246,2.032)
  rect 0.305x1.448 smd: 1(-7.256,3.099) 2(-7.256,-3.099) 3(-6.755,3.099) 4(-6.755,-3.099) 5(-6.255,3.099) 6(-6.255,-3.099) 7(-5.754,3.099) 8(-5.754,-3.099) 9(-5.254,3.099) 10(-5.254,-3.099) 11(-4.754,3.099) 12(-4.754,-3.099) 13(-4.253,3.099) 14(-4.253,-3.099) 15(-3.753,3.099) 16(-3.753,-3.099) 17(-3.252,3.099) 18(-3.252,-3.099) 19(-2.752,3.099) 20(-2.752,-3.099) 21(-2.252,3.099) 22(-2.252,-3.099) 23(-1.751,3.099) 24(-1.751,-3.099) 25(-1.251,3.099) 26(-1.251,-3.099) 27(-0.751,3.099) 28(-0.751,-3.099) 29(-0.25,3.099) 30(-0.25,-3.099) 31(0.25,3.099) 32(0.25,-3.099) 33(0.751,3.099) 34(0.751,-3.099) 35(1.251,3.099) 36(1.251,-3.099) 37(1.751,3.099) 38(1.751,-3.099) 39(2.252,3.099) 40(2.252,-3.099) 41(2.752,3.099) 42(2.752,-3.099) 43(3.252,3.099) 44(3.252,-3.099) 45(3.753,3.099) 46(3.753,-3.099) 47(4.253,3.099) 48(4.253,-3.099) 49(4.754,3.099) 50(4.754,-3.099) 51(5.254,3.099) 52(5.254,-3.099) 53(5.754,3.099) 54(5.754,-3.099) 55(6.255,3.099) 56(6.255,-3.099) 57(6.755,3.099) 58(6.755,-3.099) 59(7.256,3.099) 60(7.256,-3.099)
  rect 2.54x0.432 smd: 61(-8.445,0) 64(8.445,0)
  rect 4.699x0.432 smd: 62(-3.175,0) 63(3.175,0)
R0402
  rect 0.508x0.508 smd: 1(0,0.445) 2(0,-0.445)
SC70_TI
  rect 0.4x0.9 smd: 1(-0.65,-1.1) 2(0,-1.1) 3(0.65,-1.1) 4(0.65,1.1) 5(-0.65,1.1)
SMT38
  round 0.762 hole 0.762 unplated: (-15.113,-0.991) (15.113,0)
  round 2.413 hole 2.413 unplated: (11.43,0)
  oval 0.432x1.27 smd: 1(5.715,3.493) 2(5.715,-3.493) 3(5.08,3.493) 4(5.08,-3.493) 5(4.445,3.493) 6(4.445,-3.493) 7(3.81,3.493) 8(3.81,-3.493) 9(3.175,3.493) 10(3.175,-3.493) 11(2.54,3.493) 12(2.54,-3.493) 13(1.905,3.493) 14(1.905,-3.493) 15(1.27,3.493) 16(1.27,-3.493) 17(0.635,3.493) 18(0.635,-3.493) 19(0,3.493) 20(0,-3.493) 21(-0.635,3.493) 22(-0.635,-3.493) 23(-1.27,3.493) 24(-1.27,-3.493) 25(-1.905,3.493) 26(-1.905,-3.493) 27(-2.54,3.493) 28(-2.54,-3.493) 29(-3.175,3.493) 30(-3.175,-3.493) 31(-3.81,3.493) 32(-3.81,-3.493) 33(-4.445,3.493) 34(-4.445,-3.493) 35(-5.08,3.493) 36(-5.08,-3.493) 37(-5.715,3.493) 38(-5.715,-3.493)
  round 1.397 hole 0.889: 39(5.08,0) 40(2.54,0) 41(0,0) 42(-2.54,0) 43(-5.08,0)
SON6
  rect 0.305x0.508 smd: 1(-0.5,-0.379) 2(0,-0.379) 3(0.5,-0.379) 4(0.5,0.379) 5(0,0.379) 6(-0.5,0.379)
SOT23
  rect 1.016x1.422 smd: 1(-0.95,-1.1) 2(0.95,-1.1) 3(0,1.1)
TDFN-8
  rect 0.356x0.711 smd: 1(-0.975,-1.475) 2(-0.325,-1.475) 3(0.325,-1.475) 4(0.975,-1.475) 5(0.975,1.475) 6(0.325,1.475) 7(-0.325,1.475) 8(-0.975,1.475)
  rect 2.4x1.6 smd: 9(0,0)
TPS22902BYFPR
  round 0.203 smd: A1(-0.2,0.2) A2(0.2,0.2) B1(-0.2,-0.2) B2(0.2,-0.2)
TSLP-3-7
  rect 0.229x0.356 smd: 1(-0.189,-0.328) 2(0.189,-0.328)
  rect 0.61x0.356 smd: 3(0,0.328)
TSSOP20
  rect 1.651x0.33 smd: 1(-2.87,2.926) 2(-2.87,2.276) 3(-2.87,1.626) 4(-2.87,0.975) 5(-2.87,0.325) 6(-2.87,-0.325) 7(-2.87,-0.975) 8(-2.87,-1.626) 9(-2.87,-2.276) 10(-2.87,-2.926) 11(2.87,-2.926) 12(2.87,-2.276) 13(2.87,-1.626) 14(2.87,-0.975) 15(2.87,-0.325) 16(2.87,0.325) 17(2.87,0.975) 18(2.87,1.626) 19(2.87,2.276) 20(2.87,2.926)
unnamed
  round 1.016 smd: (0,0)
WURTH_6X3P5_TACT_SWITCH
  rect 2.311x1.499 smd: 1(-3.356,0) 2(3.356,0)
WURTH_MICRO-SD_CARD
  rect 0.8x1.5 smd: 1(0,0) 2(1.1,-0.4) 3(2.2,0) 4(3.3,0.2) 5(4.4,0) 6(5.5,0.2) 7(6.6,0) 8(7.7,0)
  rect 1.397x1.905 smd: 9(8.49,2.852) 10(-4.66,3.852)
  rect 1.803x1.397 smd: 11(6.888,-10.3) 12(1.188,-10.3)
XTAL_ECX-32
  rect 1.397x1.092 smd: 1(-1.143,-0.889) 2(1.143,-0.889) 3(1.143,0.889) 4(-1.143,0.889)

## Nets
GND: C1.2 C2.1 C3.2 C4.1 C5.2 C6.2 C7.2 C8.2 C11.2 C13.1 C15.2 C17.1 C18.2 C20.1 C23.2 C25.1 C26.2 C28.2 C29.2 C31.1 C32.2 C33.1 C34.2 C35.1 C36.1 C37.1 C38.1 C39.2 C40.2 C41.2 C42.2 C43.1 C44.1 C45.1 C46.1 C47.1 C48.2 C53.2 C54.2 C55.1 C56.2 C57.1 C58.2 C59.1 C60.2 C61.1 C62.1 C63.1 C896.2 C900.1 C903.1 C909.2 C914.2 C915.2 C916.2 C919.2 C920.2 C921.2 C922.2 C924.1 C925.1 C927.1 C928.2 C929.1 C931.1 C932.1 C933.1 C934.1 C935.1 C936.1 C937.1 C938.1 C939.1 C940.1 C943.1 C944.2 C945.2 C946.2 C953.1 C954.2 C955.2 C956.2 C957.2 C958.2 C959.2 C960.1 C961.1 C962.1 C963.1 C964.1 C965.2 D1.3(A) D2.3(A) D3.3(A) J1.61 J1.62 J1.63 J1.64 J2.3 J3.18(GND_TAB#18) J3.19(GND_TAB#19) J4.5(GND) J5.6(VSS) J5.9(CAGE#9) J5.10(CAGE#10) J5.11(CAGE#11) J5.12(CAGE#12) J7.5(SHIELD) J8.5(GND) J8.16(TD7) J8.18(TD6) J8.20(TD5) J8.22(TD4) J8.23(TD15) J8.24(TD3) J8.25(TD14) J8.26(TD2) J8.27(TD13) J8.28(TD1) J8.29(TD12) J8.31(TD11) J8.33(TD10) J8.35(TD9) J8.37(TD8) J8.38(TD0) J8.39(GND1) J8.40(GND2) J8.41(GND3) J8.42(GND4) J8.43(GND5) J10.2 J11.1 J12.1 J13.1 Q1.2(SOURCE) Q2.2(SOURCE) Q3.2(SOURCE) Q4.2(SOURCE) Q5.2(SOURCE) Q6.2(SOURCE) Q7.2(SOURCE) R1.2 R17.2 R19.2 R23.2 R26.2 R28.2 R30.2 R32.2 R34.2 R36.2 R38.2 R39.1 R42.2 R45.2 R63.1 R78.1 R101.2 R106.2 R107.1 R109.1 R113.1 R114.1 R116.1 R612.2 R667.1 R668.1 R670.1 R698.1 R5266.2 R5269.2 R5275.2 R5276.1 R5285.2 S1.1 S2.1 U1.29(VSS) U1.49(P_GND) U3.8(GND) U3.9(GND_PAD) U4.33(GND_FLAG) U5.1(GND) U6.B1(GND) U9.4(GND1) U9.17(GND2) U9.20(GND3) U9.24(AGND) U9.26(TEST) U9.33(EPAD_GND) U10.4(GND) U15.B5(GND3) U15.C1(GND1) U15.C2(GND2) U15.D5(GND4) U62.5(GND) U62.11(EPAD) U63.3(GND) U64.3(GND) U65.3(GND) U68.3(GND) U69.3(GND) U70.3(GND) Y1.2 Y1.4 Y2.2(GND) Y3.2(GND)
VCC_3.3V: C48.1 C900.2 C924.2 C928.1 L1.1 R9.1 R16.1 R47.1 R126.1 R127.1 R129.1 R5262.2 R5308.1 U6.A2(VIN) U15.D1(VOUT1_1) U15.E1(VOUT1_2) U62.9(VIN2) U62.10(VIN1)
VCC_5V: C32.1 C903.2 U3.5(IN) U15.A1(VOUT2_1) U15.B1(VOUT2_2)
VCC_12V: C3.1 C4.2 C896.1 C959.1 J1.1 J1.60 U15.A2(VIN1) U15.B3(VIN3) U15.D3(VIN4) U15.E2(VIN2)
VCCIO_HPS: C1.1 C2.2 C45.2 C909.1 C946.1 C954.1 C956.1 C957.1 C958.1 C960.2 C961.2 C962.2 C963.2 J1.2 J1.59 L2.1 R4.1 R6.1 R7.1 R10.1 R44.1 R46.1 R79.1 R80.1 R81.1 R82.1 R83.1 R84.1 R110.2 R111.2 R112.2 R115.1 R125.2 R128.2 R675.1 R686.1 R687.1 R688.1 R689.1 R690.1 R691.1 R692.2 R693.2 R694.1 R695.1 R696.1 R697.1 R5304.1 R5305.1 R5306.2 R5307.2 R5309.1 U5.2(VREF_A) U63.5(VCC) U68.5(VCC) U69.5(VCC) U70.5(VCC)
ACTIVITY_LED: J3.13(YK) L9.2
CARD_PRSTN: J1.52 R1.1
CLK125_NDO_LED_MODE: R37.2 R38.1 U1.41(CLK125_NDO_LED_MODE)
CT0: C5.1 J3.12(CT0)
CT1: C6.1 J3.6(CT1)
CT2: C7.1 J3.1(CT2)
CT3: C8.1 J3.7(CT3)
DC_PGOOD: J1.54 R671.1 U15.B4(PGOOD2) U15.D4(PGOOD1)
DIP_1: J10.1 R5284.2 R5285.1 U63.1(OE)
E_RX_CLK: R8.1 R35.2 R36.1 U1.35(RX_CLK_PHYAD2)
E_RX_DV: R11.1 R33.2 R34.1 U1.33(RX_DV_CLK125_EN)
E_RXD0: R12.1 R31.2 R32.1 U1.32(RXD0_MODE0)
E_RXD1: R13.1 R29.2 R30.1 U1.31(RXD1_MODE1)
E_RXD2: R14.1 R27.2 R28.1 U1.28(RXD2_MODE2)
E_RXD3: R15.1 R25.2 R26.1 U1.27(RXD3_MODE3)
EN: R5286.1 U5.20(EN)
ENET_1.2V_AVDDL: C23.1 C25.2 C931.2 L4.2 U1.4(AVDDL#4) U1.9(AVDDL#9)
ENET_1.2V_AVDLL_PLL: C18.1 C20.2 L3.2 U1.44(AVDDL_PLL)
ENET_1.2V_DVDDL: C29.1 C31.2 C932.2 C933.2 C934.2 C935.2 C936.2 L5.2 U1.14(DVDDL#14) U1.18(DVDDL#18) U1.23(DVDDL#23) U1.26(DVDDL#26) U1.30(DVDDL#30) U1.39(DVDDL#39)
ENET_1.8V_DVDDH: C15.1 C17.2 C938.2 C939.2 L2.2 R18.1 R22.1 R25.1 R27.1 R29.1 R31.1 R33.1 R35.1 R37.1 U1.16(DVDDH#16) U1.34(DVDDH#34) U1.40(DVDDH#40)
ENET_3.3V_AVDDH: C11.1 C13.2 C937.2 L1.2 U1.1(AVDDH#1) U1.12(AVDDH#12)
ENET_GTX_CLK: J1.15 R5311.2
ENET_INTN: J1.27 R10.2 U1.38(INT_N/PME_N2)
ENET_LED1: Q6.1(GATE) R22.2 R23.1 U1.17(LED1_PHYAD0/PME_N1)
ENET_LED2: Q4.1(GATE) R18.2 R19.1 U1.15(LED2_PHYAD1)
ENET_MDC: J1.50 R4.2 U1.36(MDC)
ENET_MDIO: J1.49 R6.2 U1.37(MDIO)
ENET_RSET: R17.1 U1.48(ISET)
ENET_RSTN: R5287.2 U1.42(RESET_N)
ENET_RX_CLK: J1.17 R8.2
ENET_RX_DV: J1.18 R11.2
ENET_RXD0: J1.21 R12.2
ENET_RXD1: J1.22 R13.2
ENET_RXD2: J1.25 R14.2
ENET_RXD3: J1.26 R15.2
ENET_TX_EN: J1.16 U1.25(TX_EN)
ENET_TXD0: J1.19 U1.19(TXD0)
ENET_TXD1: J1.20 U1.20(TXD1)
ENET_TXD2: J1.23 U1.21(TXD2)
ENET_TXD3: J1.24 U1.22(TXD3)
ENET_VDD1.2V: C26.1 C28.1 C930.2 L3.1 L4.1 L5.1 R699.1 R5265.2 U62.1(VOUT1) U62.2(VOUT2)
ENET_XI: R21.2 U1.46(XI)
FPGA_JTAG_TCK: J1.55 R117.1 R693.1
FPGA_JTAG_TDI: J1.56 R121.1 R681.1 R686.2
FPGA_JTAG_TDO: J1.58 R123.1 R688.2
FPGA_JTAG_TMS: J1.57 R119.1 R682.1 R687.2
FT232R_3V3OUT: C55.2 C56.1 R97.1 U9.16(3V3OUT)
FT232R_RXD: U9.2(RXD) U65.4(Y)
FT232R_TXD: U9.30(TXD) U63.2(A)
FT232R_VCCIO: C57.2 C58.1 C919.1 C944.1 C945.1 D4.A(ANODE) D5.A(ANODE) R97.2 R105.2 R5271.1 R5284.1 U9.1(VCCIO) U64.5(VCC) U65.5(VCC)
HPS_JTAG_TCK: J1.35 R118.1 R692.1
HPS_JTAG_TDI: J1.38 R122.1 R689.2
HPS_JTAG_TDO: J1.37 R124.1 R691.2
HPS_JTAG_TMS: J1.36 R120.1 R690.2
HPS_LED0: J1.47 Q1.1(GATE) R681.2
HPS_LED1: J1.46 Q3.1(GATE) R682.2
HPS_LED2: J1.48 Q2.1(GATE)
HPS_OSC_CLK: J1.45 R5291.2
HPS_OSC_CLK_1.8V: C953.2 C955.1 R131.1 R5309.2 Y2.4(VCC)
HPS_PB0: J1.31 U69.4(Y)
HPS_PB1: J1.32 U70.4(Y)
HPS_RESETN: J1.53 R7.2 R683.1
HPS_RESETN_1: R685.1 U68.2(A)
I2C1_SCL: J1.34 J2.1 R695.2
I2C1_SDA: J1.33 J2.2 R694.2
INTVCC: R671.2 U15.C3(INTVCC)
LDO_O: U1.43(LDO_O)
LINK_LED: J3.17(GK) L10.2
LOGIC0A: J8.30(LOGIC0A) R113.2
LOGIC0B: J8.32(LOGIC0B) R114.2
LOGIC1: J8.34(LOGIC1) R115.2
MDI_HPS_N0: J3.10(TD0_N) U1.3(TXRXM_A)
MDI_HPS_N1: J3.5(TD1_N) U1.6(TXRXM_B)
MDI_HPS_N2: J3.2(TD2_N) U1.8(TXRXM_C)
MDI_HPS_N3: J3.9(TD3_N) U1.11(TXRXM_D)
MDI_HPS_P0: J3.11(TD0_P) U1.2(TXRXP_A)
MDI_HPS_P1: J3.4(TD1_P) U1.5(TXRXP_B)
MDI_HPS_P2: J3.3(TD2_P) U1.7(TXRXP_C)
MDI_HPS_P3: J3.8(TD3_P) U1.10(TXRXP_D)
MICRO_USB_PGND: C940.2 J4.6(SHELL1) J4.7(SHELL2) J4.8(SHELL3) J4.9(SHELL4) R5266.1
MICTOR_JTAG_TCK: R117.2 R118.2 R5301.1
MICTOR_JTAG_TDI: R121.2 R122.2 R5303.1
MICTOR_JTAG_TDO: J8.11(TDO/SWO) R123.2 R124.2
MICTOR_JTAG_TMS: R119.2 R120.2 R5302.1
MICTOR_JTAG_TRSTN: J8.21(NTRST) R112.1
MICTOR_PWR1: J8.12(VTREF) R110.1
MICTOR_SRSTN: J8.9(NSRST) R684.2
MINI_USB_PGND: C943.2 J7.6(SHIELD2) J7.7(SHIELD3) R5269.1
PB_SW0: C62.2 R125.1 S1.2 U69.2(A)
PB_SW1: C63.2 R128.1 S2.2 U70.2(A)
PHY_25M_3.3V: C925.2 C927.2 R20.1 R5308.2 Y3.4(VCC)
PWN_EN: J1.51 R698.2 R5307.1 U15.B2(RUN2) U15.D2(RUN1)
PWR_ENA: R105.1 U9.11(CBUS3)
SD_3.3V: C42.1 C43.2 C44.2 C47.2 J5.4(VDD) R66.2 R67.1 U6.A1(VOUT)
SD_CLK: J1.41 R79.2 U5.10(A8)
SD_CLK_3.3V: D3.1(K1) J5.5(CLK) R76.1 U5.11(B8)
SD_CMD: J1.40 R80.2 U5.9(A7)
SD_CMD_3.3V: D3.2(K2) J5.3(CMD) R75.1 U5.12(B7)
SD_DATA0: J1.39 R81.2 U5.5(A3)
SD_DATA0_3.3V: D2.1(K1) J5.7(DAT0) R70.1 U5.16(B3)
SD_DATA1: J1.42 R82.2 U5.6(A4)
SD_DATA1_3.3V: D2.2(K2) J5.8(DAT1) R72.1 U5.15(B4)
SD_DATA2: J1.43 R83.2 U5.7(A5)
SD_DATA2_3.3V: D1.1(K1) J5.1(DAT2) R73.1 U5.14(B5)
SD_DATA3: J1.44 R84.2 U5.8(A6)
SD_DATA3_3.3V: D1.2(K2) J5.2(CD/DAT3) R74.1 R78.2 U5.13(B6)
SD_RSTN: R5289.2 R5306.1 U6.B2(ON)
TRACECTL: J8.36(TRACECTL) R116.2
UART_RESETN: R5270.2 R5271.2 U9.18(R\E\S\E\T\)
UART_RSTN: R5290.2 U64.2(A)
UART_RX: J1.30 R696.2 R5283.2 R5300.1
UART_RX_LED: R104.1 U9.21(CBUS1)
UART_TX: J1.29 R697.2 R5283.1 U65.2(A)
UART_TX_LED: R103.1 U9.22(CBUS0)
USB_5V: C33.2 C39.1 J4.1(VBUS) R54.1 U3.4(OUT)
USB_CLK: J1.3 R59.1
USB_CLKR: R59.2 U4.1(CLKOUT)
USB_CPEN: R45.1 U3.7(ON) U4.17(CPEN)
USB_D_N: J4.2(D-) U4.19(DM)
USB_D_P: J4.3(D+) U4.18(DP)
USB_DATA0: J1.6 R5292.1
USB_DATA1: J1.7 R5293.1
USB_DATA2: J1.9 R5294.1
USB_DATA3: J1.10 R5295.1
USB_DATA4: J1.11 R5296.1
USB_DATA5: J1.12 R5297.1
USB_DATA6: J1.13 R5298.1
USB_DATA7: J1.14 R5299.1
USB_DIR: J1.5 R61.1
USB_DIRR: R61.2 U4.31(DIR)
USB_ID: J4.4(ID) U4.23(ID)
USB_NXT: J1.8 R60.1
USB_NXTR: R60.2 U4.2(NXT)
USB_RBIAS: R63.2 U4.24(RBIAS)
USB_RSTN: R5288.2 U4.27(RESET)
USB_STP: J1.4 U4.29(STP)
USB_UART_5V: C59.2 C60.1 L6.1 U9.19(VCC) U10.6(VBUS)
USB_UART_CON_5V: C61.2 C920.1 J7.1(VBUS) L6.2
USB_UART_DM: C53.1 J7.2(D-) U9.15(USBDM) U10.1(D+)
USB_UART_DP: C54.1 J7.3(D+) U9.14(USBDP) U10.2(D-)
USB_VBAT: C34.1 C35.2 C914.1 R47.2 U4.20(VDD3.3) U4.21(VBAT)
USB_VBUS: R54.2 U4.22(VBUS)
USB_VDD18: C36.2 C38.2 C916.1 R44.2 U4.28(VDD1.8#28) U4.30(VDD1.8#30)
USB_VDDIO: C37.2 C915.1 R46.2 U4.8(REFSEL0) U4.11(REFSEL1) U4.14(REFSEL2) U4.32(VDDIO)
USB_VFLAGN: J1.28 R675.2 U3.2(F\L\A\G\)
USB_XI: C41.1 R62.1 U4.26(REFCLK) Y1.1
USB_XO: C40.1 R62.2 U4.25(XO) Y1.3
VREF_B: C46.2 R66.1 R5286.2 U5.19(VREF_B)
N134005839: J7.4(GND) R101.1
N134005899: D4.C(CATHODE) R103.2
N134005901: D5.C(CATHODE) R104.2
N134009559: R42.1 U3.3(SETI)
N134057943: R67.2 R70.2 R72.2 R73.2 R74.2 R75.2 R76.2
N134062955: J8.8(TRIGOUT) R107.2
N134063078: J8.14(VSUPPLY) R111.1
N134063167: J8.10(NC) R109.2
N134106197: D6.A(ANODE) R126.2
N134106201: D6.C(CATHODE) Q1.3(DRAIN)
N134106389: D8.A(ANODE) R129.2
N134106393: D8.C(CATHODE) Q3.3(DRAIN)
N134106834: D7.A(ANODE) R127.2
N134106836: D7.C(CATHODE) Q2.3(DRAIN)
N134121389: R131.2 Y2.1(EN)
N134121395: R5291.1 Y2.3(OUT)
N134242750: R667.2 U15.C4(FREQ)
N134242873: R612.1 U15.C5(SYNC/MODE)
N134242878: C922.1 U15.A3(TRACK/SS2)
N134242888: C921.1 U15.E3(TRACK/SS1)
N134243679: R456.1 R668.2
N134244009: R669.2 U15.A4(FB2)
N134244011: R669.1 R670.2
N134244826: R456.2 U15.E4(FB1)
N134266858: R683.2 R684.1 R685.2
N134303911: R5262.1 U62.7(EN)
N134304469: C929.2 U62.6(SS)
N134306474: C930.1 R39.2 R699.2 U62.3(VFB)
N134306486: R5265.1 U62.4(POK)
N134320476: R5270.1 U64.4(Y)
N134322722: J8.13(RTCK) R5275.1
N134323149: J8.6(TRACECLK) R5276.2
N134323985: R5287.1 R5288.1 R5289.1 R5290.1 U68.4(Y)
N134344647: R5298.2 U4.10(DATA6)
N134344648: R5293.2 U4.4(DATA1)
N134344649: R5295.2 U4.6(DATA3)
N134344650: R5297.2 U4.9(DATA5)
N134344651: R5292.2 U4.3(DATA0)
N134344652: R5299.2 U4.13(DATA7)
N134344653: R5294.2 U4.5(DATA2)
N134344654: R5296.2 U4.7(DATA4)
N134352854: R5300.2 U63.4(Y)
N134353275: J8.15(TCK) R5301.2
N134353287: J8.17(TMS) R5302.2
N134353299: J8.19(TDI) R5303.2
N134367002: Q4.3(DRAIN) Q5.1(GATE) R5304.2
N134368065: R20.2 Y3.1(EN)
N134368399: Q6.3(DRAIN) Q7.1(GATE) R5305.2
N134420239: L9.1 Q7.3(DRAIN)
N134420387: L10.1 Q5.3(DRAIN)
N134420624: C964.2 J3.16(GOA) R16.2
N134420965: C965.1 J3.14(YA) R9.2
N134431006: R5311.1 U1.24(GTX_CLK)
N1340630246: J8.7(TRIGIN) R106.1
N1343681570: R21.1 Y3.3(OUT)

Pads without a net: J3 15; J8 1 2 3 4; U1 13 45 47; U3 1 6; U4 12 15 16; U5 3 4 17 18; U9 3 5 6 7 8 9 10 12 13 23 25 27 28 29 31 32; U10 3 5; U15 A5 E5; U62 8; U64 1; U65 1; U68 1; U69 1; U70 1

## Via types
v1: diameter 0.61, hole 0.305, TOP to BOTTOM, 602 vias

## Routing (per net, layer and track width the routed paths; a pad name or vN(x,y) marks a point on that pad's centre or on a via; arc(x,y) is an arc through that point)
GND: length 275.6
  TOP w0.229: v1(61.01,88.85) 61.01,88.34 60.72,88.06 U62.5 59.49,88.06 v1(58.62,88.93)
  TOP w0.254: v1(73.2,85.55) 73.04,85.4 U9.17 ; U9.20 71.54,82.75 v1(71.29,82.5) ; U9.26 70.04,83.75 v1(70.15,83.64) ; U6.B1 24.05,56.59 ; v1(69.39,85.55) 69.54,85.4 U9.24 ; C964.1 64.94,72.15 v1(64.94,72.47) ; 71.04,81.49 U9.4 ; 52.14,74.88 U1.29
  TOP w0.305: R63.1 v1(45.89,56.47) ; C54.2 75.18,81.99 v1(75.87,81.99) ; C53.2 75.24,85.04 v1(75.87,85.04) ; U3.8 38.57,68.36 v1(38.66,68.28)
  TOP w0.381: C946.2 v1(67.61,81.36) ; C929.1 57.64,90.44 v1(57.7,90.38) ; v1(19.99,80.09) 19.86,80.22 R116.1 ; U15.B5 v1(46.53,92.53) ; v1(43.67,70.18) R17.2 ; U15.C2 v1(47.8,87.45) ; U15.C2 v1(47.8,88.72) ; U15.C2 v1(49.07,87.45) ; U15.C2 v1(49.07,88.72) ; Q2.2 10.78,73.55 v1(10.08,74.25) ; C40.2 49.45,58.75 v1(49.2,58.5) ; v1(68.88,88.98) 68.74,88.84 U64.3 67.6,88.84 67.36,88.6 v1(67.36,88.09) ; J8.18 27.01,86.35 27.23,86.57 v1(27.23,86.69) ; Q3.2 11.74,77.99 11.67,78.06 v1(11.1,78.06) ; R5285.2 v1(64.37,89.87) ; R19.2 v1(59.67,70.75) ; J8.33 v1(21.93,93.51) 22.56,92.88 J8.31 ; v1(53.54,57.08) 53.67,56.95 C962.1 ; v1(25.24,80.91) R113.1 R114.1 ; J8.38 v1(20.66,86.44) ; v1(31.29,93.55) 30.82,93.08 J8.5 ; J8.29 v1(23.2,93.51) 23.83,92.88 J8.27 ; v1(59.1,78.56) 59.17,78.5 C960.1 ; C944.2 v1(73.07,91.01) ; v1(67.87,84.02) U63.3 ; J8.20 v1(26.37,86.69) ; J8.24 25.1,85.89 v1(24.56,86.44) ; v1(23.67,86.31) 23.83,86.15 J8.28 ; U68.3 26.66,78.55 26.78,78.67 C909.2 v1(26.78,81.99) ; v1(64.44,77.53) U65.3 ; J8.37 v1(20.66,93.51) 21.29,92.88 J8.35 ; U15.D5 v1(50.34,92.53) ; C41.2 49.45,61.67 v1(49.2,61.42) ; v1(24.94,66.12) 25.26,66.44 C957.2 25.83,65.74 26.34,65.23 28.37,65.23 28.51,65.09 U69.3 ; R23.2 v1(59.1,72.47) ; J8.22 25.74,86.4 v1(25.45,86.69) ; R101.2 74.41,78.25 v1(74.09,77.93) ; v1(24.47,84.03) J8.26 ; v1(14.02,81.67) Q1.2 ; J8.25 v1(24.47,93.51) 25.1,92.88 J8.23 ; C945.2 v1(65.33,80.22) ; 33.76,54.11 J4.5 ; R38.2 v1(42.97,73.61) ; J8.16 27.64,85.97 27.97,86.3 28.1,86.3 v1(28.5,86.69) ; 33.07,61.17 32.32,61.91 U70.3 ; R39.1 v1(63.17,85.68) ; C956.2 v1(30.21,67.52)
  TOP w0.406: v1(33.65,61.17) 33.07,61.17
  TOP w0.508: S1.1 40.89,54.54 v1(40.89,55.45) ; C963.1 v1(14.97,81.87) ; Y3.2 34.89,71.71 v1(33.96,71.71) ; Q4.2 61.07,76.77 v1(61.07,76.77) ; S2.1 v1(59.28,54.18) ; Q5.2 v1(64.88,76.79) ; Y1.2 v1(51.61,57.48) ; Y1.4 v1(53.39,62.18)
  L2_GND w0.508: 69.24,50.09 J3.19 ; J3.19 71.83,50.09 ; J3.19 70.53,51.39 ; 26.37,87.86 J8.41 ; J8.41 27.25,88.73 ; J8.41 25.5,88.73 ; J8.41 26.37,89.61 ; 69.24,67.67 J3.18 ; J3.18 71.83,67.67 ; J3.18 70.53,68.96 ; J3.18 70.53,66.37 ; J10.2 62.2,92.15 ; J10.2 61.26,93.09 ; J10.2 61.26,91.21 ; J10.2 60.32,92.15 ; J8.39 31.45,89.61 ; J8.39 32.33,88.73 ; J8.39 30.58,88.73 ; J8.39 31.45,87.86 ; J8.43 22.17,88.73 ; J8.43 21.29,89.61 ; J8.43 21.29,87.86 ; J8.43 20.42,88.73 ; J8.42 23.83,89.61 ; J8.42 23.83,87.86 ; J8.42 22.96,88.73 ; J8.42 24.71,88.73 ; J7.5 78.16,81.66 ; J7.5 77.47,82.35 ; J7.5 76.79,81.66 ; J7.5 77.47,80.98 ; J2.3 7.29,93.16 ; J2.3 6.28,92.15 ; J2.3 8.29,92.15 ; J2.3 7.29,91.15 ; J8.40 28.91,89.61 ; J8.40 28.04,88.73 ; J8.40 29.79,88.73 ; J8.40 28.91,87.86
  L5_GND w0.508: J3.18 70.53,68.96 ; J3.18 70.53,66.37 ; J3.18 71.83,67.67 ; J3.18 69.24,67.67 ; 21.29,87.78 J8.43 ; J8.43 20.34,88.73 ; J8.43 22.25,88.73 ; J8.43 21.29,89.68 ; 6.21,92.15 J2.3 ; J2.3 7.29,93.23 ; J2.3 7.29,91.07 ; J2.3 8.37,92.15 ; 76.71,81.66 J7.5 ; J7.5 78.24,81.66 ; J7.5 77.47,80.9 ; 60.24,92.15 J10.2 ; J10.2 61.26,93.17 ; J10.2 62.28,92.15 ; J10.2 61.26,91.14 ; J3.19 70.53,51.39 ; J3.19 71.83,50.09 ; J3.19 69.24,50.09 ; J8.41 27.33,88.73 ; J8.41 26.37,87.78 ; J8.41 26.37,89.68 ; J8.41 25.42,88.73 ; 30.5,88.73 J8.39 ; J8.39 32.41,88.73 ; J8.39 31.45,87.78 ; J8.39 31.45,89.68 ; J8.40 28.91,89.68 ; J8.40 28.91,87.78 ; J8.40 29.87,88.73 ; J8.40 27.96,88.73 ; 22.88,88.73 J8.42 ; J8.42 23.83,89.68 ; J8.42 23.83,87.78 ; J8.42 24.79,88.73
  L7_GND w0.508: J2.3 7.29,93.23 ; J2.3 8.37,92.15 ; J2.3 6.21,92.15 ; J2.3 7.29,91.07 ; 20.34,88.73 J8.43 ; J8.43 21.29,87.78 ; J8.43 21.29,89.68 ; J8.43 22.25,88.73 ; 25.42,88.73 J8.41 ; J8.41 26.37,89.68 ; J8.41 27.33,88.73 ; J8.41 26.37,87.78 ; 30.5,88.73 J8.39 ; J8.39 31.45,89.68 ; J8.39 32.41,88.73 ; J8.39 31.45,87.78 ; 70.53,66.37 J3.18 ; J3.18 71.83,67.67 ; J3.18 69.24,67.67 ; J3.18 70.53,68.96 ; J8.40 28.91,89.68 ; J8.40 28.91,87.78 ; J8.40 27.96,88.73 ; J8.40 29.87,88.73 ; 77.47,80.9 J7.5 ; J7.5 76.71,81.66 ; J7.5 78.24,81.66 ; 61.26,91.14 J10.2 ; J10.2 62.28,92.15 ; J10.2 60.24,92.15 ; J10.2 61.26,93.17 ; J8.42 23.83,89.68 ; J8.42 24.79,88.73 ; J8.42 22.88,88.73 ; J8.42 23.83,87.78 ; J3.19 71.83,50.09 ; J3.19 70.53,51.39 ; J3.19 69.24,50.09
  BOTTOM w0.254: v1(64.21,72.45) 64.21,72.13 C964.1 ; R1.2 8.23,75.14 7.97,75.39 v1(7.41,75.39)
  BOTTOM w0.305: v1(15.03,57.86) D1.3 ; v1(17.13,49.74) C46.1 ; v1(74.37,82.12) 74.22,82.27 U10.4 ; v1(9.19,57.74) 8.68,57.74 8.18,57.23 D2.3 ; D3.3 v1(12.24,54.18) ; C45.1 18.27,58.05 18.97,58.75 19.22,58.75 19.47,58.5 U5.1 ; R78.1 v1(13.57,54.37)
  BOTTOM w0.381: v1(50.34,92.53) 50.21,92.66 R612.2 R667.1 ; C961.1 v1(6.27,61.8) ; R670.1 v1(45.01,92.61) ; C55.1 73.94,87.87 v1(73.94,88.9) 74.67,88.9 C56.2 ; R106.2 v1(35.29,92.53) ; R32.2 v1(50.59,82.12) ; v1(42.34,63.2) 42.34,63.82 41.98,64.18 41.29,64.18 R45.2 ; v1(30.15,65.48) 30.97,64.66 R42.2 ; R28.2 v1(53.13,82.12) ; R5276.1 v1(32.18,86.82) ; R5275.2 v1(33.26,92.53) ; R34.2 v1(49.32,82.12) ; R36.2 v1(48.05,82.12) ; R26.2 v1(54.4,82.12) ; R698.1 26.02,80.14 v1(25.24,80.91) ; R30.2 v1(51.86,82.12) ; v1(30.91,86.82) R107.1 ; R109.1 v1(29.64,86.82) ; C922.2 v1(42.59,90.07)
  BOTTOM w0.406: C63.1 v1(49.93,52.57) ; C62.1 v1(44.78,52.89) ; v1(17.95,56.59) C45.1
  BOTTOM w0.508: C924.1 34.93,80.15 34.53,79.74 v1(34.53,79.14) ; v1(49.2,62.94) 48.62,63.52 C37.1 ; Y2.2 23.44,72.82 23.41,72.85 v1(23.16,72.85) ; v1(56.31,65.99) 55.93,66.37 C11.2 ; C6.2 v1(62.28,50.24) ; C955.2 30.59,73.68 v1(30.15,74.12) 29.64,74.63 C953.1 ; C921.2 v1(54.02,89.99) ; R668.1 v1(53.32,91.96) ; C5.2 v1(56.69,52.02) ; v1(47.55,79.58) 47.04,79.07 C15.2 ; v1(58.21,73.17) 58.09,73.29 C939.1 ; Q7.2 v1(66.78,76.79) ; v1(41.32,77.55) 41.11,77.33 C925.1 C927.1 ; v1(58.09,78.69) 58.34,78.95 C29.2 ; C18.2 43.1,73.48 v1(42.97,73.61) ; Q6.2 v1(62.97,76.79) ; v1(33.45,72.34) 33.58,72.47 33.58,73.3 C954.2 ; C8.2 v1(57.37,65.69) ; C915.2 35.48,58.63 35.99,58.12 v1(35.99,57.41) ; C7.2 v1(63.17,68.39)
  vias: v1(5.89,82.5) v1(5.89,79.58) v1(5.89,77.42) v1(5.89,75.14) v1(5.89,72.85) v1(5.89,70.56) v1(5.89,68.4) v1(5.89,65.99) v1(5.89,64.72) v1(5.89,63.32) v1(5.89,59.26) v1(5.89,56.97) v1(5.89,55.07) v1(5.89,49.74) v1(6.02,93.55) v1(6.02,90.88) v1(6.02,88.72) v1(6.02,84.91) v1(7.92,49.74) v1(8.43,93.55) v1(9.83,49.74) v1(10.08,57.74) v1(10.33,93.55) v1(10.84,60.28) v1(11.73,60.28) v1(11.98,49.74) v1(12.49,93.55) v1(13.89,49.74) v1(14.65,93.55) v1(14.78,80.98) v1(14.78,80.09) v1(14.78,79.07) v1(14.78,76.94) v1(15.03,75.77) v1(15.67,60.81) v1(15.67,49.74) v1(15.87,77.98) v1(15.87,71.63) v1(15.87,65.28) v1(15.87,59.51) v1(16.56,81.74) v1(16.81,93.55) v1(16.81,84.28) v1(16.81,79.07) v1(16.81,77.29) v1(17.45,83.39) v1(17.57,82.37) v1(18.72,49.74) v1(19.1,93.55) v1(19.35,61.8) v1(19.99,49.74) v1(20.49,61.8) v1(21.13,76.15) v1(21.38,74.5) v1(22.02,49.74) v1(24.43,49.74) v1(24.75,55.77) v1(24.76,54.36) v1(25.22,81.82) v1(26.34,55.63) v1(26.44,54.41) v1(27.43,53.93) v1(32.43,93.55) v1(33.83,77.17) v1(33.96,54.56) v1(34.59,93.55) v1(34.84,54.56) v1(35.63,68.28) v1(35.63,67.39) v1(35.63,66.5) v1(35.86,54.56) v1(36.6,68.28) v1(36.6,67.39) v1(36.6,66.5) v1(36.75,93.55) v1(37.51,86.57) v1(38.53,86.57) v1(38.91,93.55) v1(39.54,87.58) v1(39.54,86.57) v1(41.2,93.55) v1(42.21,81.49) v1(42.34,62.05) v1(42.34,60.91) v1(42.97,81.1) v1(43.48,63.2) v1(43.48,62.05) v1(43.48,60.91) v1(43.73,93.55) v1(44.5,63.2) v1(44.5,62.05) v1(44.5,60.91) v1(45.64,72.98) v1(45.89,93.55) v1(46.78,71.71) v1(47.04,56.47) v1(47.55,51.29) v1(47.57,50.47) v1(47.6,49.63) v1(47.8,93.55) v1(48.51,51.26) v1(48.51,50.42) v1(48.46,49.63) v1(49.32,76.15) v1(49.32,74.12) v1(49.32,72.09) v1(50.21,93.55) v1(51.39,74.13) v1(51.48,76.15) v1(52.5,93.55) v1(52.5,72.21) v1(53.39,87.77) v1(53.51,88.85) v1(53.51,76.15) v1(53.51,74.12) v1(53.51,72.09) v1(54.72,88.98) v1(54.66,87.71) v1(58.34,84.28) v1(58.34,83.26) v1(58.64,87.7) v1(58.66,86.38) v1(58.66,85.38) v1(58.8,50.83) v1(59.1,93.55) v1(59.1,87.06) v1(59.55,86.35) v1(59.58,88.93) v1(59.57,87.73) v1(59.66,90.34) v1(59.86,49.61) v1(61.26,93.55) v1(63.8,93.55) v1(65.58,93.55) v1(65.58,49.74) v1(70.15,81.36) v1(71.8,93.42) v1(71.8,91.9) v1(72.44,83.64) v1(72.44,81.36) v1(72.82,93.42) v1(72.82,91.9) v1(74.34,93.42) v1(75.36,93.42) v1(76.25,93.42) v1(78.28,93.55) v1(80.18,93.55) v1(80.18,76.41) v1(80.18,75.26)
VCC_3.3V: length 39.2
  TOP w0.254: U62.10 56.95,86.06 ; U62.9 56.95,86.56 ; 23.03,58.37 23.09,58.32 U6.A2 ; R16.1 63.23,71.77 62.72,72.28 v1(62.66,72.28)
  TOP w0.381: R129.1 6.65,74.82 v1(6.65,75.77) ; v1(54.91,90.63) 55.11,90.43 R5262.2 ; R126.1 6.46,80.72 v1(6.4,80.72) ; R127.1 v1(7.03,70.31)
  L6_SIG w0.508: v1(55.29,85.17) 53.9,85.17 53.51,84.79 37.91,84.79 36.11,83 v1(36.11,82.37)
  BOTTOM w0.254: v1(63.42,72.47) 63.42,71.83 63.36,71.77 R16.1
  BOTTOM w0.508: R5308.1 C924.2 35.86,81.04 35.86,81.04 35.86,82.12 v1(36.11,82.37) ; L1.1 53.9,66.12 56.44,63.58 v1(59.23,63.58)
  vias: v1(19.86,55.45) v1(20.88,55.45) v1(49.04,55.2) v1(49.78,55.81) v1(55.29,84.28) v1(56.18,85.17) v1(56.18,84.28) v1(57.07,85.17) v1(57.07,84.28)
VCC_5V:
  vias: v1(37.64,65.36) v1(38.53,66.25) v1(38.53,65.36) v1(39.42,66.25) v1(39.42,65.36) v1(43.73,82.5) v1(43.73,81.49) v1(44.75,82.5) v1(44.75,81.49) v1(45.64,82.5) v1(45.64,81.49)
VCC_12V: length 3.6
  TOP w0.381: U15.A2 v1(45.26,87.45) ; U15.E2 v1(51.61,87.45) ; U15.B3 v1(46.53,88.72) ; U15.D3 v1(50.34,89.99)
  vias: v1(9.57,85.93) v1(9.57,84.91) v1(10.59,85.93) v1(10.59,84.91) v1(11.6,85.93) v1(11.6,84.91) v1(17.32,63.58) v1(18.21,63.58) v1(43.61,89.23) v1(43.61,88.34) v1(44.5,89.23) v1(44.5,88.34)
VCCIO_HPS: length 61
  TOP w0.254: v1(32.86,66.47) 32.86,66.89 R675.1 ; R691.1 15.22,74.44 v1(15.16,74.5) 15.03,74.37 R695.1 ; R6.1 v1(42.85,77.68) ; R694.1 16.68,70.37 R697.1 v1(16.62,69.48) R696.1 ; R4.1 v1(42.97,79.07) ; R10.1 v1(42.85,76.28)
  TOP w0.381: v1(20.88,80.85) 20.94,80.91 R115.1 ; v1(55.83,57.08) 55.7,56.95 C962.2 ; U70.5 31.02,66.1 31.1,66.18 C956.1 v1(31.1,67.52) ; v1(65.33,81.36) C946.1 66.02,81.89 65.2,82.72 U63.5 ; v1(20.49,78.95) 20.24,78.69 R687.1 ; R125.2 28.6,61.17 v1(29.21,60.56) ; U69.5 27.21,67.15 27.03,67.33 C957.1 v1(24.88,67.33) ; R5304.1 v1(62.02,69.42) ; v1(23.54,78.06) 23.54,77.5 23.34,77.29 R7.1 ; v1(59.1,77.68) 59.17,77.61 C960.2 ; v1(27.99,81.99) 27.67,81.68 C909.1 27.67,80.08 27.9,79.85 U68.5 ; v1(25.19,64.72) 25.19,62.05 24.81,61.67 R5306.2
  TOP w0.406: R128.2 32.62,58.59 v1(33.83,57.38)
  TOP w0.508: C963.2 v1(16.56,82.76)
  BOTTOM w0.254: R686.1 v1(8.05,76.41) ; v1(8.18,72.09) R690.1 R689.1 ; R688.1 v1(8.05,77.68)
  BOTTOM w0.305: v1(28.11,77.04) 26.97,78.18 R5307.2 ; U5.2 20.12,59.12 19.73,59.51 18.53,59.51 C45.2 ; R692.2 v1(20.68,72.41) ; R693.2 v1(23.54,78.06)
  BOTTOM w0.381: R5304.1 62.02,70.82 v1(62.78,70.06) ; v1(8.56,61.17) 7.92,61.8 C961.2 ; R112.2 v1(19.61,91.77)
  BOTTOM w0.406: C45.2 17.26,58.94 v1(17.06,58.75)
  BOTTOM w0.508: R5309.1 32.75,76.78 C954.1 33.82,75.58 32.69,74.45 32.69,71.83 v1(32.81,71.71) ; v1(24.81,82.76) 25.57,83.52 R111.2 R110.2
  vias: v1(11.35,61.93) v1(12.37,61.93) v1(20.88,81.74) v1(20.88,79.96) v1(23.29,64.72) v1(34.39,56.64) v1(34.95,57.36) v1(42.96,80.19) v1(50.85,65.23) v1(51.1,64.34)
ACTIVITY_LED: length 28.9
  BOTTOM w0.254: J3.13 76.88,61.17 74.6,58.88 66.98,58.88 66.09,59.77 66.09,69.17 66.47,69.55 66.47,70.25 L9.2
CARD_PRSTN: length 4
  BOTTOM w0.142: J1.52 11.02,76.83 9.76,75.58 R1.1
CLK125_NDO_LED_MODE: length 5
  TOP w0.142: U1.41 47.29,74.88 46.91,74.5 46.15,74.5 45.77,74.88 R37.2 R38.1
CT0: length 3.4
  BOTTOM w0.508: J3.12 60.63,52.02 C5.1
CT1: length 3.6
  BOTTOM w0.508: J3.6 63.93,52.11 63.92,52.1 C6.1
CT2: length 3.5
  BOTTOM w0.508: C7.1 J3.1
CT3: length 3.1
  BOTTOM w0.508: J3.7 58.28,64.98 C8.1
DC_PGOOD: length 54.2
  TOP w0.142: U15.B4 v1(46.53,91.26) ; U15.D4 v1(50.34,91.26)
  L3_SIG w0.155: v1(46.53,91.26) 47.16,91.9 49.7,91.9 v1(50.34,91.26)
  L6_SIG w0.155: v1(46.53,91.26) 45.89,91.9 33.19,91.9 31.42,90.12 30.91,90.12 29.64,91.39 25.95,91.39 25.19,90.63 18.84,90.63 17.06,88.85 17.06,85.93 13.38,82.25 13.38,77.93 v1(13.98,77.33)
  BOTTOM w0.142: v1(50.34,91.26) 49.91,90.83 49.91,90.52 R671.1 ; J1.54 v1(13.98,77.33)
DIP_1: length 11.1
  TOP w0.142: U63.1 66.23,82.72 65.73,83.22 65.73,85.13 65.26,85.6 R5284.2 R5285.1 65.26,90.69 J10.1
E_RX_CLK: length 8.1
  TOP w0.142: U1.35 49.14,78.11 48.94,78.31 48.94,79.33 v1(48.69,79.58) 48.3,79.97 48.24,79.97 R35.2
  BOTTOM w0.142: v1(48.69,79.58) 48.05,80.22 R36.1 48.5,80.53 48.69,80.72 48.69,82.88 48.5,83.07 R8.1
E_RX_DV: length 7.9
  TOP w0.142: R33.2 49.48,80 49.48,79.81 v1(49.7,79.58) 50.21,79.07 50.21,78.18 50.14,78.11 U1.33
  BOTTOM w0.142: v1(49.7,79.58) 49.32,79.96 R34.1 49.77,80.53 49.96,80.72 49.96,82.88 49.77,83.07 R11.1
